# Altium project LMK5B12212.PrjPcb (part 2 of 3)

## Sheet LMK5B12212_Power.SchDoc
size 431 x 279 mm; Date: Not shown in title block; ApprovedBy: Not shown in title block; CheckedBy: Not shown in title block; Author: Not shown in title block; CompanyName: Not shown in title block; Engineer: Not shown in title block; Organization: Not shown in title block; Address1: Not shown in title block; Address2: Not shown in title block; Address3: Not shown in title block; Address4: Not shown in title block; DocumentNumber: 2; Revision: Use project parameter SCH_Rev; SheetNumber: 2; SheetTotal: 3; PageSetup: Record=PageOptions¦CenterHorizontal=True¦CenterVertical=True¦PrintScale=1.00¦XCorrection=1.00¦YCorrection=1.00¦PrintKind=0¦BorderSize=5000000¦LeftOffset=0¦BottomOffset=0¦Orientation=2¦PaperLength=1000¦PaperWidth=1000¦Scale=100¦PaperSource=15¦PrintQuality=600¦MediaType=1¦DitherType=10¦PaperKind=Letter¦PrintScaleMode=1
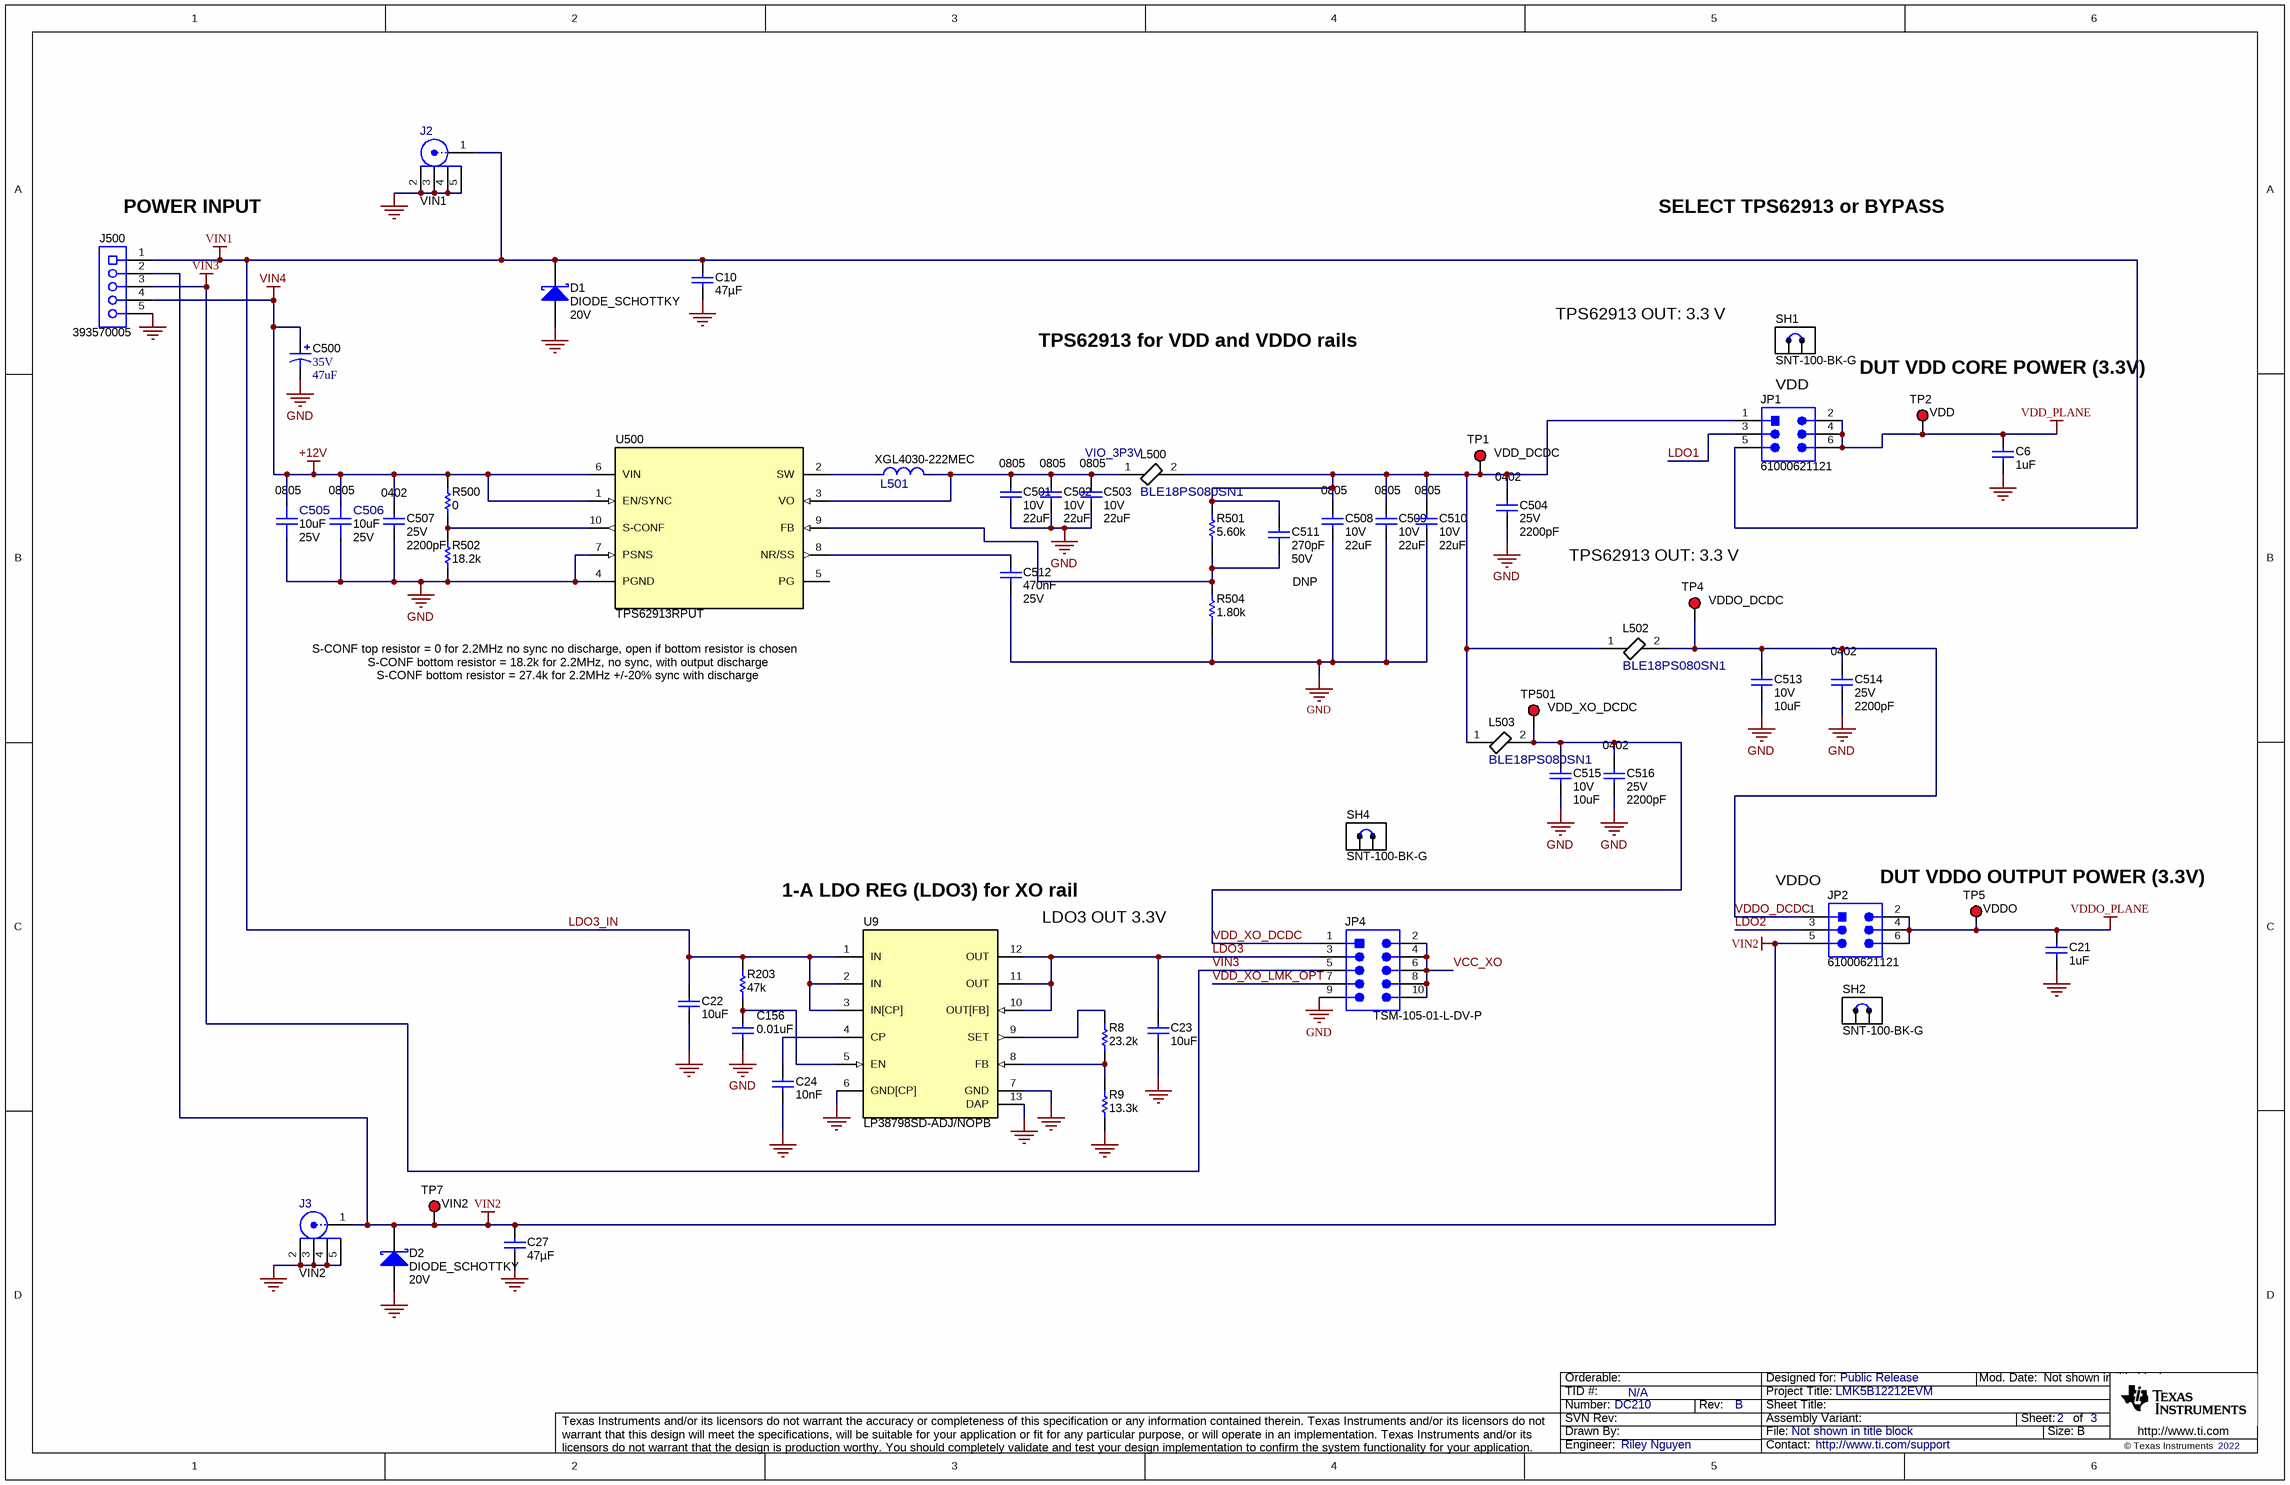
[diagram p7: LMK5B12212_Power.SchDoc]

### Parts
C6  ValueDisplayed: 1uF  [0603]  (hidden comment: Capacitor)
C10  ValueDisplayed: 47µF  [0805_HV]  (hidden comment: GRM21BR61A476ME15L)
C21  ValueDisplayed: 1uF  [0603]  (hidden comment: Capacitor)
C22  ValueDisplayed: 10uF  [0603]  (hidden comment: Capacitor)
C23  ValueDisplayed: 10uF  [0603]  (hidden comment: Capacitor)
C24  ValueDisplayed: 10nF  [0603]  (hidden comment: Capacitor)
C27  ValueDisplayed: 47µF  [0805_HV]  (hidden comment: GRM21BR61A476ME15L)
C156  ValueDisplayed: 0.01uF  [0603]  (hidden comment: Capacitor)
C500  VDC_V: 35V  ValueDisplayed: 47uF  [7343-43]  (hidden comment: T495X476K035ATE300)
C501  Cap_Case: 0805  VDC_V: 10V  ValueDisplayed: 22uF  [0805L]  (hidden comment: C2012X7S1A226M125AC)
C502  Cap_Case: 0805  VDC_V: 10V  ValueDisplayed: 22uF  [0805L]  (hidden comment: C2012X7S1A226M125AC)
C503  Cap_Case: 0805  VDC_V: 10V  ValueDisplayed: 22uF  [0805L]  (hidden comment: C2012X7S1A226M125AC)
C504  VDC_V: 25V  ValueDisplayed: 2200pF  [0402]  (hidden comment: GRM155R71E222KA01D)
C505  PackageReference: 0805  ValueDisplayed: 10uF  VDC_V: 25V  [FP-C2012X7S1E106K125AC_0805-MFG]  (hidden comment: C2012X7S1E106K125AC)
C506  PackageReference: 0805  ValueDisplayed: 10uF  VDC_V: 25V  [FP-C2012X7S1E106K125AC_0805-MFG]  (hidden comment: C2012X7S1E106K125AC)
C507  VDC_V: 25V  ValueDisplayed: 2200pF  [0402]  (hidden comment: GRM155R71E222KA01D)
C508  Cap_Case: 0805  VDC_V: 10V  ValueDisplayed: 22uF  [0805L]  (hidden comment: C2012X7S1A226M125AC)
C509  Cap_Case: 0805  VDC_V: 10V  ValueDisplayed: 22uF  [0805L]  (hidden comment: C2012X7S1A226M125AC)
C510  Cap_Case: 0805  VDC_V: 10V  ValueDisplayed: 22uF  [0805L]  (hidden comment: C2012X7S1A226M125AC)
C511  Cap_F: 270pF  VDC_V: 50V  [0402]  (hidden comment: UMK105CG271JV-F)
C512  Cap_F: 470nF  VDC_V: 25V  [0603]  (hidden comment: C1608X7R1E474K080AE)
C513  VDC_V: 10V  ValueDisplayed: 10uF  [0603]  (hidden comment: GRM188Z71A106MA73D)
C514  VDC_V: 25V  ValueDisplayed: 2200pF  [0402]  (hidden comment: GRM155R71E222KA01D)
C515  VDC_V: 10V  ValueDisplayed: 10uF  [0603]  (hidden comment: GRM188Z71A106MA73D)
C516  VDC_V: 25V  ValueDisplayed: 2200pF  [0402]  (hidden comment: GRM155R71E222KA01D)
D1  DIODE_SCHOTTKY  value 20V  [SMA]
D2  DIODE_SCHOTTKY  value 20V  [SMA]
J2  VIN1  [FP-CON-SMA-EDGE-S_CONN_JACK-MFG]
J3  VIN2  [FP-CON-SMA-EDGE-S_CONN_JACK-MFG]
J500  393570005  [Molex_0393570005]
JP1  61000621121  [Wurth_61000621121]
JP2  61000621121  [Wurth_61000621121]
JP4  TSM-105-01-L-DV-P  [Samtec_TSM-105-01-x-DV]
L500  BLE18PS080SN1  [FP-BLE18PS080SN1_0603-MFG]
L501  XGL4030-222MEC  [FP-XGL4030-222MEC_SMT_IND_4MM0_4MM0-MFG]
L502  BLE18PS080SN1  [FP-BLE18PS080SN1_0603-MFG]
L503  BLE18PS080SN1  [FP-BLE18PS080SN1_0603-MFG]
R8  ValueDisplayed: 23.2k  [0603]  (hidden comment: CRCW060323K2FKEA)
R9  ValueDisplayed: 13.3k  [0603]  (hidden comment: CRCW060313K3FKEA)
R203  ValueDisplayed: 47k  [0603]  (hidden comment: Resistor)
R500  ValueDisplayed: 0  [0603]  (hidden comment: ERJ-3GEY0R00V)
R501  ValueDisplayed: 5.60k  [0603]  (hidden comment: RG1608P-562-B-T5)
R502  ValueDisplayed: 18.2k  [0603]  (hidden comment: CRCW060318K2FKEA)
R504  ValueDisplayed: 1.80k  [0603]  (hidden comment: RT0603BRD071K8L)
SH1  SNT-100-BK-G  [SNT-100-BK-G]
SH2  SNT-100-BK-G  [SNT-100-BK-G]
SH4  SNT-100-BK-G  [SNT-100-BK-G]
TP1  VDD_DCDC  [Keystone5000]
TP2  VDD  [Keystone5000]
TP4  VDDO_DCDC  [Keystone5000]
TP5  VDDO  [Keystone5000]
TP7  VIN2  [Keystone5000]
TP501  VDD_XO_DCDC  [Keystone5000]
U9  LP38798SD-ADJ/NOPB  [DNT0012B]
U500  TPS62913RPUT  [RPU0010A]

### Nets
+12V: C500.1(+) C505.2 C506.2 C507.1 J500.4 R500.2 U500.1(EN/SYNC) U500.6(VIN)  [also labelled VIN4]
GND: C6.1 C10.2 C21.1 C22.2 C23.2 C24.2 C27.2 C156.2 C500.2(-) C501.2 C502.2 C503.2 C504.2 C505.1 C506.1 C507.2 C508.2 C509.2 C510.2 C512.2 C513.2 C514.2 C515.2 C516.2 D1.2(A) D2.2(A) J2.2 J2.3 J2.4 J2.5 J3.2 J3.3 J3.4 J3.5 J500.5 JP4.9 R9.1 R502.1 R504.1 U9.6(GND[CP]) U9.7(GND) U9.13(DAP) U500.4(PGND) U500.7(PSNS)
LDO3_IN: C10.1 C22.1 D1.1(K) J2.1 J500.1 JP1.5 R203.1 U9.1(IN) U9.2(IN) U9.3(IN[CP])  [also labelled VIN1]
VCC_XO: JP4.2 JP4.4 JP4.6 JP4.8 JP4.10
VDD_PLANE: C6.2 JP1.2 JP1.4 JP1.6 TP2.1
VDDO_PLANE: C21.2 JP2.2 JP2.4 JP2.6 TP5.1
VIN2: C27.1 D2.1(K) J3.1 J500.2 JP2.5 TP7.1
VIN3: J500.3 JP4.5
LDO1: JP1.3
LDO2: JP2.3
LDO3: C23.1 JP4.3 U9.10(OUT[FB]) U9.11(OUT) U9.12(OUT)
VDD_XO_DCDC: C515.1 C516.1 JP4.1 L503.2 TP501.1
VDD_XO_LMK_OPT: JP4.7
VDDO_DCDC: C513.1 C514.1 JP2.1 L502.2 TP4.1
NetC24_1: C24.1 U9.4(CP)
NetC156_1: C156.1 R203.2 U9.5(EN)
NetC501_1: C501.1 C502.1 C503.1 L500.1 L501.2 U500.3(VO)
NetC504_1: C504.1 C508.1 C509.1 C510.1 C511.1 JP1.1 L500.2 L502.1 L503.1 R501.2 TP1.1
NetC511_2: C511.2 R501.1 R504.2 U500.9(FB)
NetC512_1: C512.1 U500.8(NR/SS)
NetL501_1: L501.1 U500.2(SW)
NetR8_1: R8.1 R9.2 U9.8(FB)
NetR8_2: R8.2 U9.9(SET)
NetR500_1: R500.1 R502.2 U500.10(S-CONF)

Not connected (* = marked no-connect by the designer): U500 5(PG)

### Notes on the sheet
- (near J500) POWER INPUT
- SELECT TPS62913 or BYPASS
- TPS62913 for VDD and VDDO rails
- TPS62913 OUT: 3.3 V
- (near TP2) DUT VDD CORE POWER (3.3V)
- VDD
- VIO_3P3V
- (near TP4) TPS62913 OUT: 3.3 V
- DNP
- S-CONF top resistor = 0 for 2.2MHz no sync no discharge, open if bottom resistor is chosen
- S-CONF bottom resistor = 18.2k for 2.2MHz, no sync, with output discharge
- S-CONF bottom resistor = 27.4k for 2.2MHz +/-20% sync with discharge
- 1-A LDO REG (LDO3) for XO rail
- (near JP2) VDDO
- DUT VDDO OUTPUT POWER (3.3V)
- LDO3 OUT 3.3V

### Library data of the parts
C6 C21 = CMP-0006869-5: CAP, CERM, 1 uF, 10 V, +/- 10%, X5R, 0603; Manufacturer: Kemet; PartNumber: C0603C105K8PACTU; Polarized: N; TaMax_C: 85°C; TaMin_C: -55°C; VDC_V: 10V; Cap_F: 1µF; Value: 1uF; Value1: Unknown; AEC Category: Q200; SizeArea_mm2: 1.28; SizeAreaWB_mm2: 4.68; SizeX_mm: 1.6; SizeY_mm: 0.8; SizeZ_mm: 1; U/M: EA
C10 C27 = CMP-0078699-1: CAP, CERM, 47 µF, 10 V,+/- 20%, X5R, 0805; Manufacturer: MuRata; Polarized: N; Value: 47uF; U/M: EA; VDC_V: 10V; TaMin_C: -55°C; TaMax_C: 85°C; Cap_Case: 0805; SizeArea_mm2: 2.5; SizeAreaWB_mm2: 6.75; SizeX_mm: 2; SizeY_mm: 1.25; SizeZ_mm: 1.45; AEC Category: Q200; Green_Lifecycle: Active; Green_REACh: Passed
C22-C24 = CMP-0007003-5: CAP, CERM, 10 uF, 10 V, +/- 20%, X5R, 0603; PartNumber: C1608X5R1A106M080AC; Manufacturer: TDK; Polarized: N; Value: 10uF; U/M: EA; Cap_F: 10µF; ESR_ohm: 7.8m; Value1: 0.0078 ohm; VDC_V: 10V; IRMS_A: 1.85A; TaMin_C: -55°C; TaMax_C: 85°C; SizeArea_mm2: 1.28; SizeAreaWB_mm2: 4.68; SizeX_mm: 1.6; SizeY_mm: 0.8; SizeZ_mm: 1; AEC Category: Q200
C156 = CMP-0006850-4: CAP, CERM, 0.01 uF, 50 V, +/- 5%, X7R, 0603; PartNumber: C0603C103J5RACTU; Manufacturer: Kemet; Polarized: N; Value: 0.01uF; U/M: EA; Cap_F: 10nF; Value1: Unknown; VDC_V: 50V; TaMin_C: -55°C; TaMax_C: 125°C; SizeArea_mm2: 1.28; SizeAreaWB_mm2: 4.68; SizeX_mm: 1.6; SizeY_mm: 0.8; SizeZ_mm: 1; AEC Category: Q200
C500 = CMP-0011835-2: CAP, TA, 47 uF, 35 V, +/- 10%, 0.3 ohm, SMD; Manufacturer: Kemet; TaMin_C: -55°C; ESR_ohm: 3d; Polarized: Y; SizeAreaWB_mm2: 58.59; Value1: 0.3 ohm; U/M: EA; Value: 47uF; TaMax_C: 125°C; SizeZ_mm: 4.3; SizeX_mm: 7.3; Cap_Case: X; SizeArea_mm2: 31.39; CompType: Capacitor; Cap_F: 47µF; IRMS_A: 6.67dA; AEC Category: Q200
C501-C503 C508-C510 = CMP-0007890-1: CAP, CERM, 22 uF, 10 V, +/- 20%, X7S, 0805; Manufacturer: TDK; TaMin_C: -55°C; ESR_ohm: 2.05m; Polarized: N; SizeAreaWB_mm2: 6.75; Value1: 0.00205 ohm; U/M: EA; Value: 22uF; TaMax_C: 125°C; SizeZ_mm: 1.45; SizeX_mm: 2; SizeY_mm: 1.25; SizeArea_mm2: 2.5; Cap_F: 22µF; IRMS_A: 4.55587A; AEC Category: Q200
C504 C507 C514 C516 = CMP-0006663-2: CAP, CERM, 2200 pF, 25 V, +/- 10%, X7R, 0402; Manufacturer: MuRata; TaMin_C: -55°C; Polarized: N; SizeAreaWB_mm2: 3; Value1: Unknown; U/M: EA; Value: 2200pF; TaMax_C: 125°C; SizeZ_mm: 0.6; SizeX_mm: 1; SizeY_mm: 0.5; Cap_F: 2.2nF; AEC Category: Q200
C505 C506 = CMP-0089528-1: 10µF ±10% 25V Ceramic Capacitor X7S 0805 (2012 Metric); Manufacturer: TDK; TempCo: 22%; SizeZ_mm: 1.5mm; AEC Qualified: No
C511 = CMP-0087076-3: CAP CER 270PF 50V NP0 0402; Manufacturer: Taiyo Yuden; Tolerance_%: 5%; SizeZ_mm: 0.55mm; AEC Qualified: No; TempCo: 30ppm/°C
C512 = CMP-0750175-1: CAP, CERM, 0.47 µF, 25 V,+/- 10%, X7R, 0603; Manufacturer: TDK; AEC Qualified: N; TaMax_C: 125°C; U/M: EA; AEC Category: Q200; Value: 0.47uF; SizeX_mm: 1.6; SizeAreaWB_mm2: 4.68; SizeZ_mm: 1; SizeY_mm: 0.8; SizeArea_mm2: 1.28; ValueDisplayed: 0.47µF; TaMin_C: -55°C
C513 C515 = CMP-0007497-5: CAP, CERM, 10 uF, 10 V, +/- 20%, X7R, 0603; Manufacturer: MuRata; TaMin_C: -55°C; Polarized: N; SizeAreaWB_mm2: 4.68; Value1: Unknown; U/M: EA; Value: 10uF; TaMax_C: 125°C; SizeZ_mm: 1; SizeX_mm: 1.6; SizeY_mm: 0.8; SizeArea_mm2: 1.28; Cap_F: 10µF; AEC Category: Q200
D1 D2 = CMP-0028399-2: Diode, Schottky, 20 V, 2 A, SMA; PartNumber: B220A-13-F; Manufacturer: Diodes Inc.; Vf_V: 5dV; Value1: 2A; Value2: 0.5V; TJmax_C: 150°C; RJC_CperW: 20; AEC Category: Q101; Green_Lifecycle: Active; Green_REACh: Passed; SizeArea_mm2: 16.3228; SizeAreaWB_mm2: 37.3428; SizeX_mm: 5.59; SizeY_mm: 2.92; SizeZ_mm: 2.87
J2 J3 = CMP-0088000-4: CONN SMA JACK STR EDGE MNT; Manufacturer: RF Solutions Ltd.; PartNumber: CON-SMA-EDGE-S; ContactFinish: Gold; Shrouded: true
J500 = CMP-0080926-1: Terminal Block, 3.5mm, 5x1, Tin, TH; Manufacturer: Molex; Pitch_mm: 3.5; Gender: Female; Voltage_V: 300V; Row_Count: 1; Current_A: 17.5A; Cert_UL: Y
JP1 JP2 = CMP-0079534-2: Header, 2.54mm, 3x2, Gold, SMT; Manufacturer: Wurth Elektronik; Pitch_mm: 2.54; Gender: Male; Cert_UL: Y; Current_A: 3A; Voltage_V: 250V; Shrouded: N; Row_Count: 2
JP4 = CMP-0055598-2: Header, 2.54mm, 5x2, Gold, SMT; Manufacturer: Samtec; Current_A: 5.4A; Green_Lifecycle: Active; Shrouded: N; Gender: Male; Cert_CSA: Y; Green_REACh: Passed; Voltage_V: 475V; Row_Count: 2; RowSpacing_mm: 2.54
L500 L502 L503 = CMP-0087072-1: Bead inductor BLE series, 8A; Manufacturer: Murata; SizeZ_mm: 0.75mm; AEC Qualified: No; Material: Ferrite
L501 = CMP-0089541-1: Inductor Power Shielded Wirewound 2.2uH 20% 1MHz Composite 8.7A 15mOhm DCR Automotive T/R; Manufacturer: Coilcraft; Shrouded: true; SizeZ_mm: 3.1mm; AEC Grade: Grade 1; AEC Qualified: Yes; Isat: 3.1A; Ind_H: 2.2µH; Self Resonant Frequency: 40MHz; DCR_ohm: 0.015; Standoff Height: 0.16mm; TaMin_C: -40°C; TaMax_C: +125°C
R8 = CMP-0022228-4: RES, 23.2 k, 1%, 0.1 W, AEC-Q200 Grade 0, 0603; Manufacturer: Vishay-Dale; Value: 23.2k; Value_Code: 23k2; Power_W: 100mW; Value2: 0.1W; VDC_V: 75V; TempCo: 100 ppm/C; EIA_Code: E96; SizeArea_mm2: 1.28; SizeX_mm: 1.6; SizeY_mm: 0.8; SizeZ_mm: 1; AEC Category: Q200; AEC Qualified: Y; AEC Grade: 0
R9 = CMP-0022043-4: RES, 13.3 k, 1%, 0.1 W, AEC-Q200 Grade 0, 0603; Manufacturer: Vishay-Dale; Value: 13.3k; Value_Code: 13k3; Power_W: 100mW; Value2: 0.1W; VDC_V: 75V; TempCo: 100 ppm/C; EIA_Code: E96; SizeArea_mm2: 1.28; SizeX_mm: 1.6; SizeY_mm: 0.8; SizeZ_mm: 1; AEC Category: Q200; AEC Qualified: Y; AEC Grade: 0
R203 = CMP-0025814-4: RES, 47 k, 5%, 0.1 W, AEC-Q200 Grade 0, 0603; PartNumber: CRCW060347K0JNEA; Manufacturer: Vishay-Dale; Value: 47k; Value_Code: 47k0; Power_W: 100mW; Value2: 0.1W; VDC_V: 75V; TempCo: 200 ppm/C; EIA_Code: E24; SizeArea_mm2: 1.28; SizeX_mm: 1.6; SizeY_mm: 0.8; SizeZ_mm: 1; AEC Category: Q200; AEC Qualified: Y; AEC Grade: 0
R500 = CMP-0025874-4: RES, 0, 5%, 0.1 W, AEC-Q200 Grade 0, 0603; Manufacturer: Panasonic; Power_W: 100mW; TempCo: 600 ppm/C; Value_Code: 0000; Value: 0; EIA_Code: E24; SizeX_mm: 1.6; SizeY_mm: 0.8; SizeZ_mm: 1; Value2: 0.1W; SizeArea_mm2: 1.28; AEC Qualified: Y; VDC_V: 50V; AEC Category: Q200; SizeAreaWB_mm2: 4.68
R501 = CMP-0023576-3: RES, 5.60 k, 0.1%, 0.1 W, 0603; Manufacturer: Susumu Co Ltd; Power_W: 100mW; TempCo: 25 ppm/C; Value_Code: 5k60; U/M: EA; Value: 5.60k; Res_ohm: 5.6k; SizeX_mm: 1.6; SizeY_mm: 0.8; SizeZ_mm: 1; Value2: 0.1W; SizeArea_mm2: 1.28; VDC_V: 75V; AEC Category: Q200
R502 = CMP-0022097-4: RES, 18.2 k, 1%, 0.1 W, AEC-Q200 Grade 0, 0603; Manufacturer: Vishay-Dale; Power_W: 100mW; TempCo: 100 ppm/C; Value_Code: 18k2; Value: 18.2k; EIA_Code: E96; SizeX_mm: 1.6; SizeY_mm: 0.8; SizeZ_mm: 1; Value2: 0.1W; SizeArea_mm2: 1.28; AEC Qualified: Y; VDC_V: 75V; AEC Category: Q200; AEC Grade: 0
R504 = CMP-0023914-3: RES, 1.80 k, 0.1%, 0.1 W, 0603; Manufacturer: Yageo America; Power_W: 100mW; TempCo: 25 ppm/C; Value_Code: 1k80; U/M: EA; Value: 1.80k; EIA_Code: E192; Res_ohm: 1.8k; SizeX_mm: 1.6; SizeY_mm: 0.8; SizeZ_mm: 1; Value2: 0.1W; SizeArea_mm2: 1.28; VDC_V: 75V; AEC Category: Q200
SH1 SH2 SH4 = CMP-0003623-3: Shunt, 100mil, Gold plated, Black; Manufacturer: Samtec; Alternate Manufacturer: 3M; Alternate PartNumber: 969102-0000-DA; Value: 1x2; Note: You can "mate" this to a header by matching the designator.  i.e. use SH-J3 for header J3
TP1 TP2 TP4 TP5 TP7 TP501 = CMP-0055137-1: Test Point, Miniature, Red, TH; Manufacturer: Keystone; CNHeader: FALSE; ContactFinish: Silver; CT: TRUE; Green_Lifecycle: Active; Green_REACh: Passed
U9 = CMP-0066007-2: 800-mA Ultra-Low-Noise, High-PSRR LDO, DNT0012B (WSON-12); Manufacturer: Texas Instruments; SizeZ_mm: 0.8; SizeX_mm: 4.0; SizeArea_mm2: 16.0; CompType: IC; U/M: EA; SizeAreaWB_mm2: 25.0
U500 = CMP-0860321-2: 3A Low Noise and Low Ripple buck converter, RPU0010A (VQFN-10); Alternate Manufacturer: Texas Instruments; SizeArea_mm2: 4; SizeAreaWB_mm2: 9; AEC Category: Q200; SizeY_mm: 2; CompType: IC; SizeZ_mm: 1; AEC Qualified: N

## Sheet LMK5B12212_Power_Alternate.SchDoc
size 431 x 279 mm; Date: Not shown in title block; ApprovedBy: Not shown in title block; CheckedBy: Not shown in title block; Author: Not shown in title block; CompanyName: Not shown in title block; Engineer: Not shown in title block; Organization: Not shown in title block; Address1: Not shown in title block; Address2: Not shown in title block; Address3: Not shown in title block; Address4: Not shown in title block; DocumentNumber: 2; Revision: Use project parameter SCH_Rev; SheetNumber: 2; SheetTotal: 3; PageSetup: Record=PageOptions¦CenterHorizontal=True¦CenterVertical=True¦PrintScale=1.00¦XCorrection=1.00¦YCorrection=1.00¦PrintKind=0¦BorderSize=5000000¦LeftOffset=0¦BottomOffset=0¦Orientation=2¦PaperLength=1000¦PaperWidth=1000¦Scale=100¦PaperSource=15¦PrintQuality=600¦MediaType=1¦DitherType=10¦PaperKind=Letter¦PrintScaleMode=1
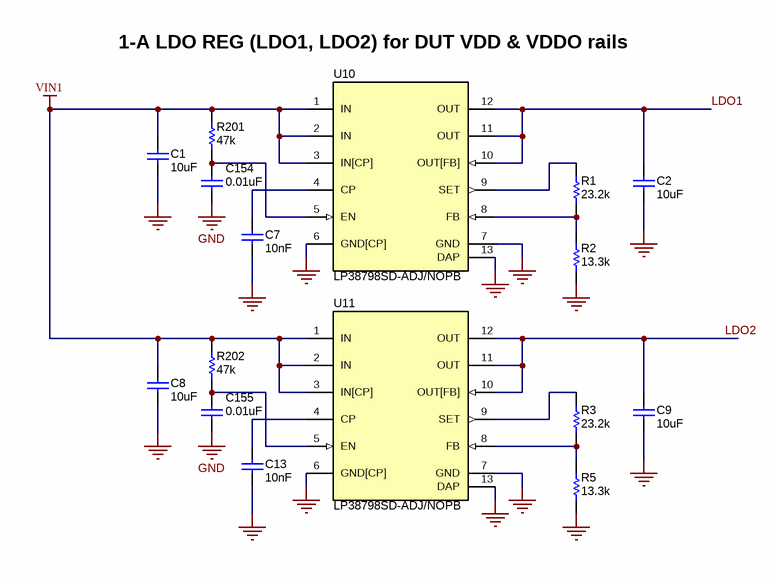
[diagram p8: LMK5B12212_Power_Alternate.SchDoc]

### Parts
C1  ValueDisplayed: 10uF  [0603]  (hidden comment: Capacitor)
C2  ValueDisplayed: 10uF  [0603]  (hidden comment: Capacitor)
C7  ValueDisplayed: 10nF  [0603]  (hidden comment: Capacitor)
C8  ValueDisplayed: 10uF  [0603]  (hidden comment: Capacitor)
C9  ValueDisplayed: 10uF  [0603]  (hidden comment: Capacitor)
C13  ValueDisplayed: 10nF  [0603]  (hidden comment: Capacitor)
C154  ValueDisplayed: 0.01uF  [0603]  (hidden comment: Capacitor)
C155  ValueDisplayed: 0.01uF  [0603]  (hidden comment: Capacitor)
R1  ValueDisplayed: 23.2k  [0603]  (hidden comment: CRCW060323K2FKEA)
R2  ValueDisplayed: 13.3k  [0603]  (hidden comment: CRCW060313K3FKEA)
R3  ValueDisplayed: 23.2k  [0603]  (hidden comment: CRCW060323K2FKEA)
R5  ValueDisplayed: 13.3k  [0603]  (hidden comment: CRCW060313K3FKEA)
R201  ValueDisplayed: 47k  [0603]  (hidden comment: Resistor)
R202  ValueDisplayed: 47k  [0603]  (hidden comment: Resistor)
U10  LP38798SD-ADJ/NOPB  [DNT0012B]
U11  LP38798SD-ADJ/NOPB  [DNT0012B]

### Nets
GND: C1.2 C2.2 C7.2 C8.2 C9.2 C13.2 C154.2 C155.2 R2.1 R5.1 U10.6(GND[CP]) U10.7(GND) U10.13(DAP) U11.6(GND[CP]) U11.7(GND) U11.13(DAP)
VIN1: C1.1 C8.1 R201.1 R202.1 U10.1(IN) U10.2(IN) U10.3(IN[CP]) U11.1(IN) U11.2(IN) U11.3(IN[CP])  [project net LDO3_IN]
LDO1: C2.1 U10.10(OUT[FB]) U10.11(OUT) U10.12(OUT)
LDO2: C9.1 U11.10(OUT[FB]) U11.11(OUT) U11.12(OUT)
NetC7_1: C7.1 U10.4(CP)
NetC13_1: C13.1 U11.4(CP)
NetC154_1: C154.1 R201.2 U10.5(EN)
NetC155_1: C155.1 R202.2 U11.5(EN)
NetR1_1: R1.1 R2.2 U10.8(FB)
NetR1_2: R1.2 U10.9(SET)
NetR3_1: R3.1 R5.2 U11.8(FB)
NetR3_2: R3.2 U11.9(SET)

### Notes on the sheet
- 1-A LDO REG (LDO1, LDO2) for DUT VDD & VDDO rails

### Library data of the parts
C1 C2 C7-C9 C13 = CMP-0007003-5: as C22 on sheet LMK5B12212_Power
C154 C155 = CMP-0006850-4: as C156 on sheet LMK5B12212_Power
R1 R3 = CMP-0022228-4: as R8 on sheet LMK5B12212_Power
R2 R5 = CMP-0022043-4: as R9 on sheet LMK5B12212_Power
R201 R202 = CMP-0025814-4: as R203 on sheet LMK5B12212_Power
U10 U11 = CMP-0066007-2: as U9 on sheet LMK5B12212_Power

## Sheet LMK5B12212_PowerDist.SchDoc
size 431 x 279 mm; Date: Not shown in title block; ApprovedBy: Not shown in title block; CheckedBy: Not shown in title block; Author: Not shown in title block; CompanyName: Not shown in title block; Engineer: Not shown in title block; Organization: Not shown in title block; Address1: Not shown in title block; Address2: Not shown in title block; Address3: Not shown in title block; Address4: Not shown in title block; DocumentNumber: 2; Revision: Use project parameter SCH_Rev; SheetNumber: 2; SheetTotal: 3; PageSetup: Record=PageOptions¦CenterHorizontal=True¦CenterVertical=True¦PrintScale=1.00¦XCorrection=1.00¦YCorrection=1.00¦PrintKind=0¦BorderSize=5000000¦LeftOffset=0¦BottomOffset=0¦Orientation=2¦PaperLength=1000¦PaperWidth=1000¦Scale=100¦PaperSource=15¦PrintQuality=600¦MediaType=1¦DitherType=10¦PaperKind=Letter¦PrintScaleMode=1
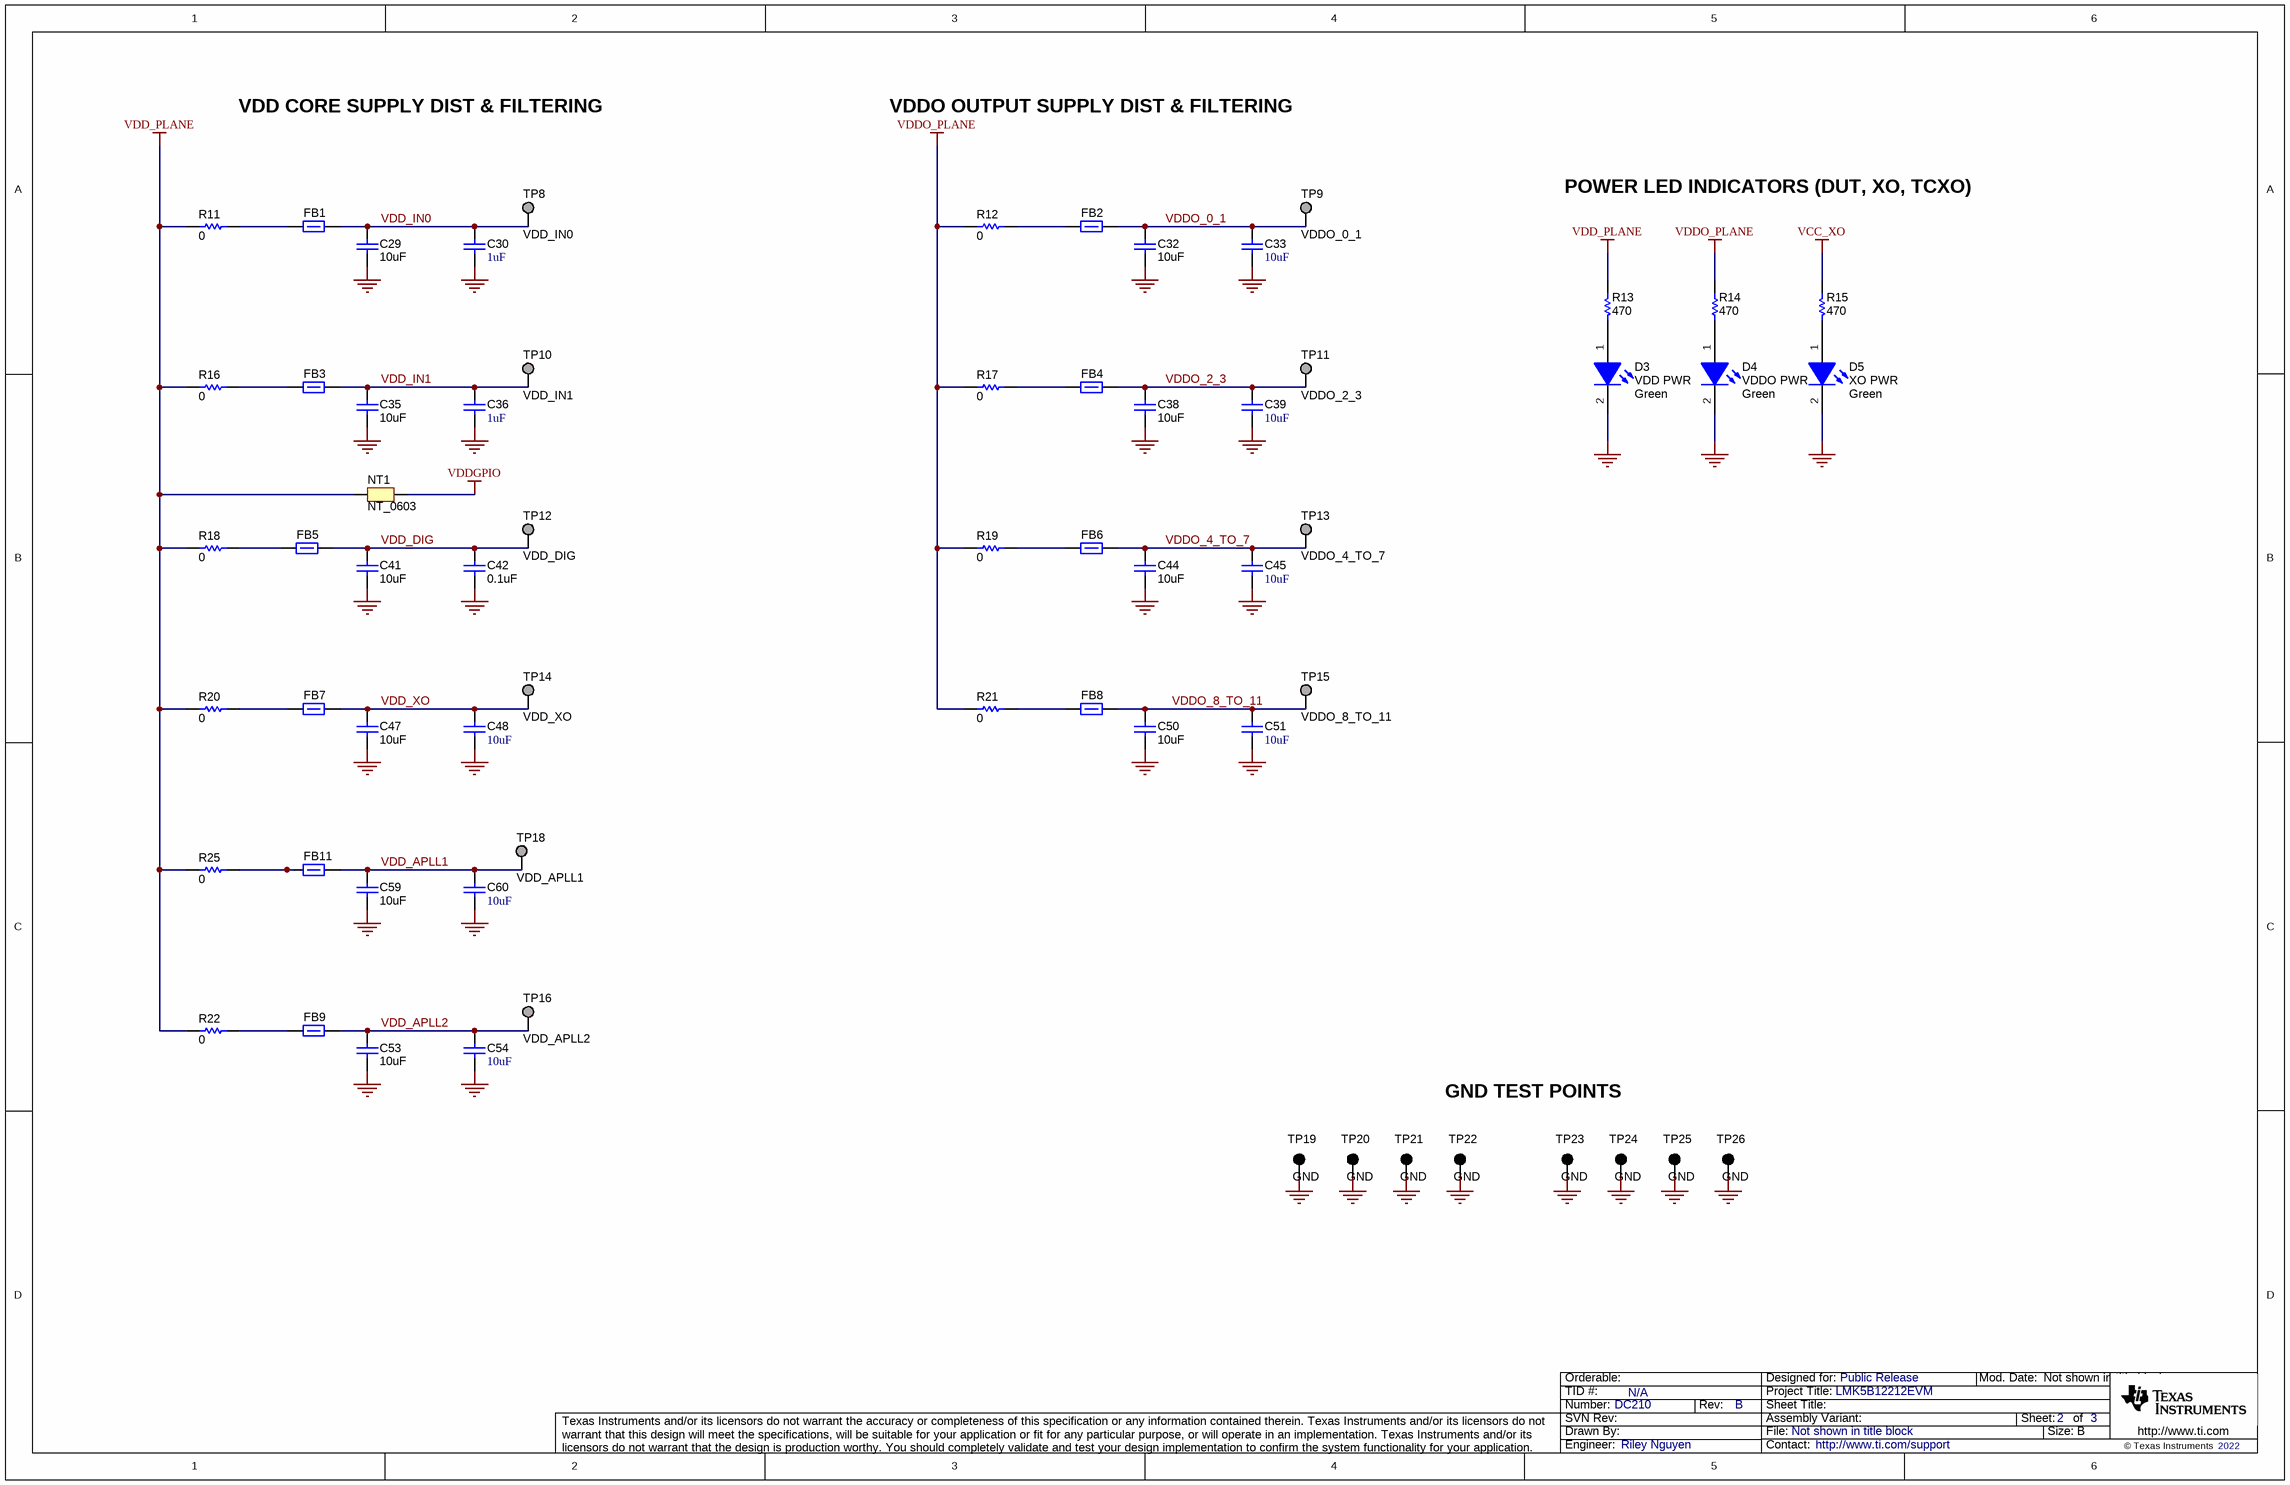
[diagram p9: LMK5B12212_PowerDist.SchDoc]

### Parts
C29  ValueDisplayed: 10uF  [0603L]  (hidden comment: Capacitor)
C30  ValueDisplayed: 1uF  [0402L]  (hidden comment: Capacitor)
C32  ValueDisplayed: 10uF  [0603L]  (hidden comment: Capacitor)
C33  ValueDisplayed: 10uF  [0402L]  (hidden comment: Capacitor)
C35  ValueDisplayed: 10uF  [0603L]  (hidden comment: Capacitor)
C36  ValueDisplayed: 1uF  [0402L]  (hidden comment: Capacitor)
C38  ValueDisplayed: 10uF  [0603L]  (hidden comment: Capacitor)
C39  ValueDisplayed: 10uF  [0402L]  (hidden comment: Capacitor)
C41  ValueDisplayed: 10uF  [0603L]  (hidden comment: Capacitor)
C42  ValueDisplayed: 0.1uF  [0402L]  (hidden comment: Capacitor)
C44  ValueDisplayed: 10uF  [0603L]  (hidden comment: Capacitor)
C45  ValueDisplayed: 10uF  [0402L]  (hidden comment: Capacitor)
C47  ValueDisplayed: 10uF  [0603L]  (hidden comment: Capacitor)
C48  ValueDisplayed: 10uF  [0402L]  (hidden comment: Capacitor)
C50  ValueDisplayed: 10uF  [0603L]  (hidden comment: Capacitor)
C51  ValueDisplayed: 10uF  [0402L]  (hidden comment: Capacitor)
C53  ValueDisplayed: 10uF  [0603L]  (hidden comment: Capacitor)
C54  ValueDisplayed: 10uF  [0402L]  (hidden comment: Capacitor)
C59  ValueDisplayed: 10uF  [0603L]  (hidden comment: Capacitor)
C60  ValueDisplayed: 10uF  [0402L]  (hidden comment: Capacitor)
D3  VDD PWR  value Green  [LED_LTST-C190]
D4  VDDO PWR  value Green  [LED_LTST-C190]
D5  XO PWR  value Green  [LED_LTST-C190]
FB1  BLM18SG221TN1D  [0603L]  (value not drawn)
FB2  BLM18SG221TN1D  [0603L]  (value not drawn)
FB3  BLM18SG221TN1D  [0603L]  (value not drawn)
FB4  BLM18SG221TN1D  [0603L]  (value not drawn)
FB5  BLM18SG221TN1D  [0603L]  (value not drawn)
FB6  BLM18SG221TN1D  [0603L]  (value not drawn)
FB7  BLM18SG221TN1D  [0603L]  (value not drawn)
FB8  BLM18SG221TN1D  [0603L]  (value not drawn)
FB9  BLM18SG221TN1D  [0603L]  (value not drawn)
FB11  BLM18SG221TN1D  [0603L]  (value not drawn)
NT1  NT_0603  [NetTie_0603]  (net tie, no BOM)
R11  ValueDisplayed: 0  [0603]  (hidden comment: CRCW06030000Z0EA)
R12  ValueDisplayed: 0  [0603]  (hidden comment: CRCW06030000Z0EA)
R13  ValueDisplayed: 470  [0603]  (hidden comment: Resistor)
R14  ValueDisplayed: 470  [0603]  (hidden comment: Resistor)
R15  ValueDisplayed: 470  [0603]  (hidden comment: Resistor)
R16  ValueDisplayed: 0  [0603]  (hidden comment: CRCW06030000Z0EA)
R17  ValueDisplayed: 0  [0603]  (hidden comment: CRCW06030000Z0EA)
R18  ValueDisplayed: 0  [0603]  (hidden comment: CRCW06030000Z0EA)
R19  ValueDisplayed: 0  [0603]  (hidden comment: CRCW06030000Z0EA)
R20  ValueDisplayed: 0  [0603]  (hidden comment: CRCW06030000Z0EA)
R21  ValueDisplayed: 0  [0603]  (hidden comment: CRCW06030000Z0EA)
R22  ValueDisplayed: 0  [0603]  (hidden comment: CRCW06030000Z0EA)
R25  ValueDisplayed: 0  [0603]  (hidden comment: CRCW06030000Z0EA)
TP8  VDD_IN0  [TP_SM_1MM]  (no BOM)
TP9  VDDO_0_1  [TP_SM_1MM]  (no BOM)
TP10  VDD_IN1  [TP_SM_1MM]  (no BOM)
TP11  VDDO_2_3  [TP_SM_1MM]  (no BOM)
TP12  VDD_DIG  [TP_SM_1MM]  (no BOM)
TP13  VDDO_4_TO_7  [TP_SM_1MM]  (no BOM)
TP14  VDD_XO  [TP_SM_1MM]  (no BOM)
TP15  VDDO_8_TO_11  [TP_SM_1MM]  (no BOM)
TP16  VDD_APLL2  [TP_SM_1MM]  (no BOM)
TP18  VDD_APLL1  [TP_SM_1MM]  (no BOM)
TP19  GND  [Keystone5001]
TP20  GND  [Keystone5001]
TP21  GND  [Keystone5001]
TP22  GND  [Keystone5001]
TP23  GND  [Keystone5001]
TP24  GND  [Keystone5001]
TP25  GND  [Keystone5001]
TP26  GND  [Keystone5001]

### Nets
GND: C29.2 C30.1 C32.2 C33.1 C35.2 C36.1 C38.2 C39.1 C41.2 C42.1 C44.2 C45.1 C47.2 C48.1 C50.2 C51.1 C53.2 C54.1 C59.2 C60.1 D3.2(K) D4.2(K) D5.2(K) TP19.1 TP20.1 TP21.1 TP22.1 TP23.1 TP24.1 TP25.1 TP26.1
VCC_XO: R15.1
VDD_PLANE: NT1.2 R11.2 R13.1 R16.2 R18.2 R20.2 R22.2 R25.2
VDDGPIO: NT1.1
VDDO_PLANE: R12.2 R14.1 R17.2 R19.2 R21.2
VDD_APLL1: C59.1 C60.2 FB11.2 TP18.1
VDD_APLL2: C53.1 C54.2 FB9.2 TP16.1
VDD_DIG: C41.1 C42.2 FB5.2 TP12.1
VDD_IN0: C29.1 C30.2 FB1.2 TP8.1
VDD_IN1: C35.1 C36.2 FB3.2 TP10.1
VDD_XO: C47.1 C48.2 FB7.2 TP14.1
VDDO_0_1: C32.1 C33.2 FB2.2 TP9.1
VDDO_2_3: C38.1 C39.2 FB4.2 TP11.1
VDDO_4_TO_7: C44.1 C45.2 FB6.2 TP13.1
VDDO_8_TO_11: C50.1 C51.2 FB8.2 TP15.1
NetD3_1: D3.1(A) R13.2
NetD4_1: D4.1(A) R14.2
NetD5_1: D5.1(A) R15.2
NetFB1_1: FB1.1 R11.1
NetFB2_1: FB2.1 R12.1
NetFB3_1: FB3.1 R16.1
NetFB4_1: FB4.1 R17.1
NetFB5_1: FB5.1 R18.1
NetFB6_1: FB6.1 R19.1
NetFB7_1: FB7.1 R20.1
NetFB8_1: FB8.1 R21.1
NetFB9_1: FB9.1 R22.1
NetFB11_1: FB11.1 R25.1

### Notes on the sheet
- VDD CORE SUPPLY DIST & FILTERING
- VDDO OUTPUT SUPPLY DIST & FILTERING
- POWER LED INDICATORS (DUT, XO, TCXO)
- GND TEST POINTS

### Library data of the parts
C29 C32 C35 C38 C41 C44 C47 C50 C53 C59 = CMP-0007003-5: CAP, CERM, 10 uF, 10 V, +/- 20%, X5R, 0603; PartNumber: C1608X5R1A106M080AC; Manufacturer: TDK; Polarized: N; Value: 10uF; U/M: EA; Cap_F: 10µF; ESR_ohm: 7.8m; Value1: 0.0078 ohm; VDC_V: 10V; IRMS_A: 1.85A; TaMin_C: -55°C; TaMax_C: 85°C; Cap_Case: 0603; SizeArea_mm2: 1.28; SizeAreaWB_mm2: 4.68; SizeX_mm: 1.6; SizeY_mm: 0.8; SizeZ_mm: 1; AEC Category: Q200
C30 C36 = CMP-0064971-2: CAP, CERM, 1 uF, 10 V,+/- 10%, X6S, 0402; PartNumber: GRM155C81A105KA12D; Manufacturer: MuRata; Polarized: N; Value: 1uF; U/M: EA; Cap_F: 1µF; Value1: Unknown; VDC_V: 10V; TaMin_C: -55°C; TaMax_C: 105°C; Cap_Case: 0402; SizeArea_mm2: 0.5; SizeAreaWB_mm2: 3; SizeX_mm: 1; SizeZ_mm: 0.6; AEC Category: Q200
C33 C39 C45 C48 C51 C54 C60 = CMP-0006564-3: CAP, CERM, 10 uF, 10 V, +/- 20%, X5R, 0402; PartNumber: GRM155R61A106ME11D; Manufacturer: MuRata; Polarized: N; Value: 10uF; U/M: EA; Cap_F: 10µF; Value1: Unknown; VDC_V: 10V; TaMin_C: -55°C; TaMax_C: 85°C; Cap_Case: 0402; SizeArea_mm2: 0.5; SizeAreaWB_mm2: 3; SizeX_mm: 1; SizeZ_mm: 0.6; AEC Category: Q200
C42 = CMP-0006259-2: CAP, CERM, 0.1 uF, 10 V, +/- 10%, X5R, 0402; PartNumber: C1005X5R1A104K050BA; Manufacturer: TDK; Polarized: N; Value: 0.1uF; U/M: EA; Cap_F: 100nF; Value1: Unknown; VDC_V: 10V; TaMin_C: -55°C; TaMax_C: 85°C; Cap_Case: 0402; SizeArea_mm2: 0.5; SizeAreaWB_mm2: 3; SizeX_mm: 1; SizeZ_mm: 0.6; AEC Category: Q200
D3-D5 = CMP-0002827-3: LED, Green, SMD; Manufacturer: Lite-On; PartNumber: LTST-C190GKT; Vf_V: 2.1V; Io_A: 20mA; Power_TotalModule: 100mW; Value1: 0.1W
FB1-FB9 FB11 = CMP-0003353-2: Ferrite Bead, 220 ohm @ 100 MHz, 2.5 A, 0603; Manufacturer: MuRata; Value: 220 ohm; Imax_A: 2.5A; DCR_ohm: 0.04; Value1: 0.04 ohm; ZTyp@100MHz_Ohm: 220; SizeArea_mm2: 1.28; SizeAreaWB_mm2: 4.68; SizeX_mm: 1.6; SizeY_mm: 0.8; SizeZ_mm: 1
NT1 = CMP-0078142-3: Single point connection between nets.
R11 R12 R16-R22 R25 = CMP-0025697-4: RES, 0, 5%, 0.1 W, AEC-Q200 Grade 0, 0603; Manufacturer: Vishay-Dale; Power_W: 100mW; TempCo: 200 ppm/C; Value_Code: 0000; Value: 0; EIA_Code: E24; SizeX_mm: 1.6; SizeY_mm: 0.8; SizeZ_mm: 1; Value2: 0.1W; SizeArea_mm2: 1.28; AEC Qualified: Y; VDC_V: 75V; AEC Category: Q200
R13-R15 = CMP-0025813-4: RES, 470, 5%, 0.1 W, AEC-Q200 Grade 0, 0603; PartNumber: CRCW0603470RJNEA; Manufacturer: Vishay-Dale; Value: 470; Value_Code: 470R; Power_W: 100mW; Value2: 0.1W; VDC_V: 75V; TempCo: 200 ppm/C; EIA_Code: E24; SizeArea_mm2: 1.28; SizeX_mm: 1.6; SizeY_mm: 0.8; SizeZ_mm: 1; AEC Category: Q200; AEC Qualified: Y; AEC Grade: 0
TP8-TP16 TP18 = CMP-0003825-1: 1mm Test Point, SMT; Manufacturer: Any
TP19-TP26 = CMP-0055138-1: Test Point, Miniature, Black, TH; Manufacturer: Keystone; ContactFinish: Silver; CNHeader: FALSE; CT: TRUE; Green_Lifecycle: Active; Green_REACh: Passed

## Sheet LMK5B12212_USB2ANY.SchDoc
size 431 x 279 mm; Date: Not shown in title block; ApprovedBy: Not shown in title block; CheckedBy: Not shown in title block; Author: Not shown in title block; CompanyName: Not shown in title block; Engineer: Not shown in title block; Organization: Not shown in title block; Address1: Not shown in title block; Address2: Not shown in title block; Address3: Not shown in title block; Address4: Not shown in title block; DocumentNumber: 2; Revision: Use project parameter SCH_Rev; SheetNumber: 2; SheetTotal: 3; PageSetup: Record=PageOptions¦CenterHorizontal=True¦CenterVertical=True¦PrintScale=1.00¦XCorrection=1.00¦YCorrection=1.00¦PrintKind=0¦BorderSize=5000000¦LeftOffset=0¦BottomOffset=0¦Orientation=2¦PaperLength=1000¦PaperWidth=1000¦Scale=100¦PaperSource=15¦PrintQuality=600¦MediaType=1¦DitherType=10¦PaperKind=Letter¦PrintScaleMode=1
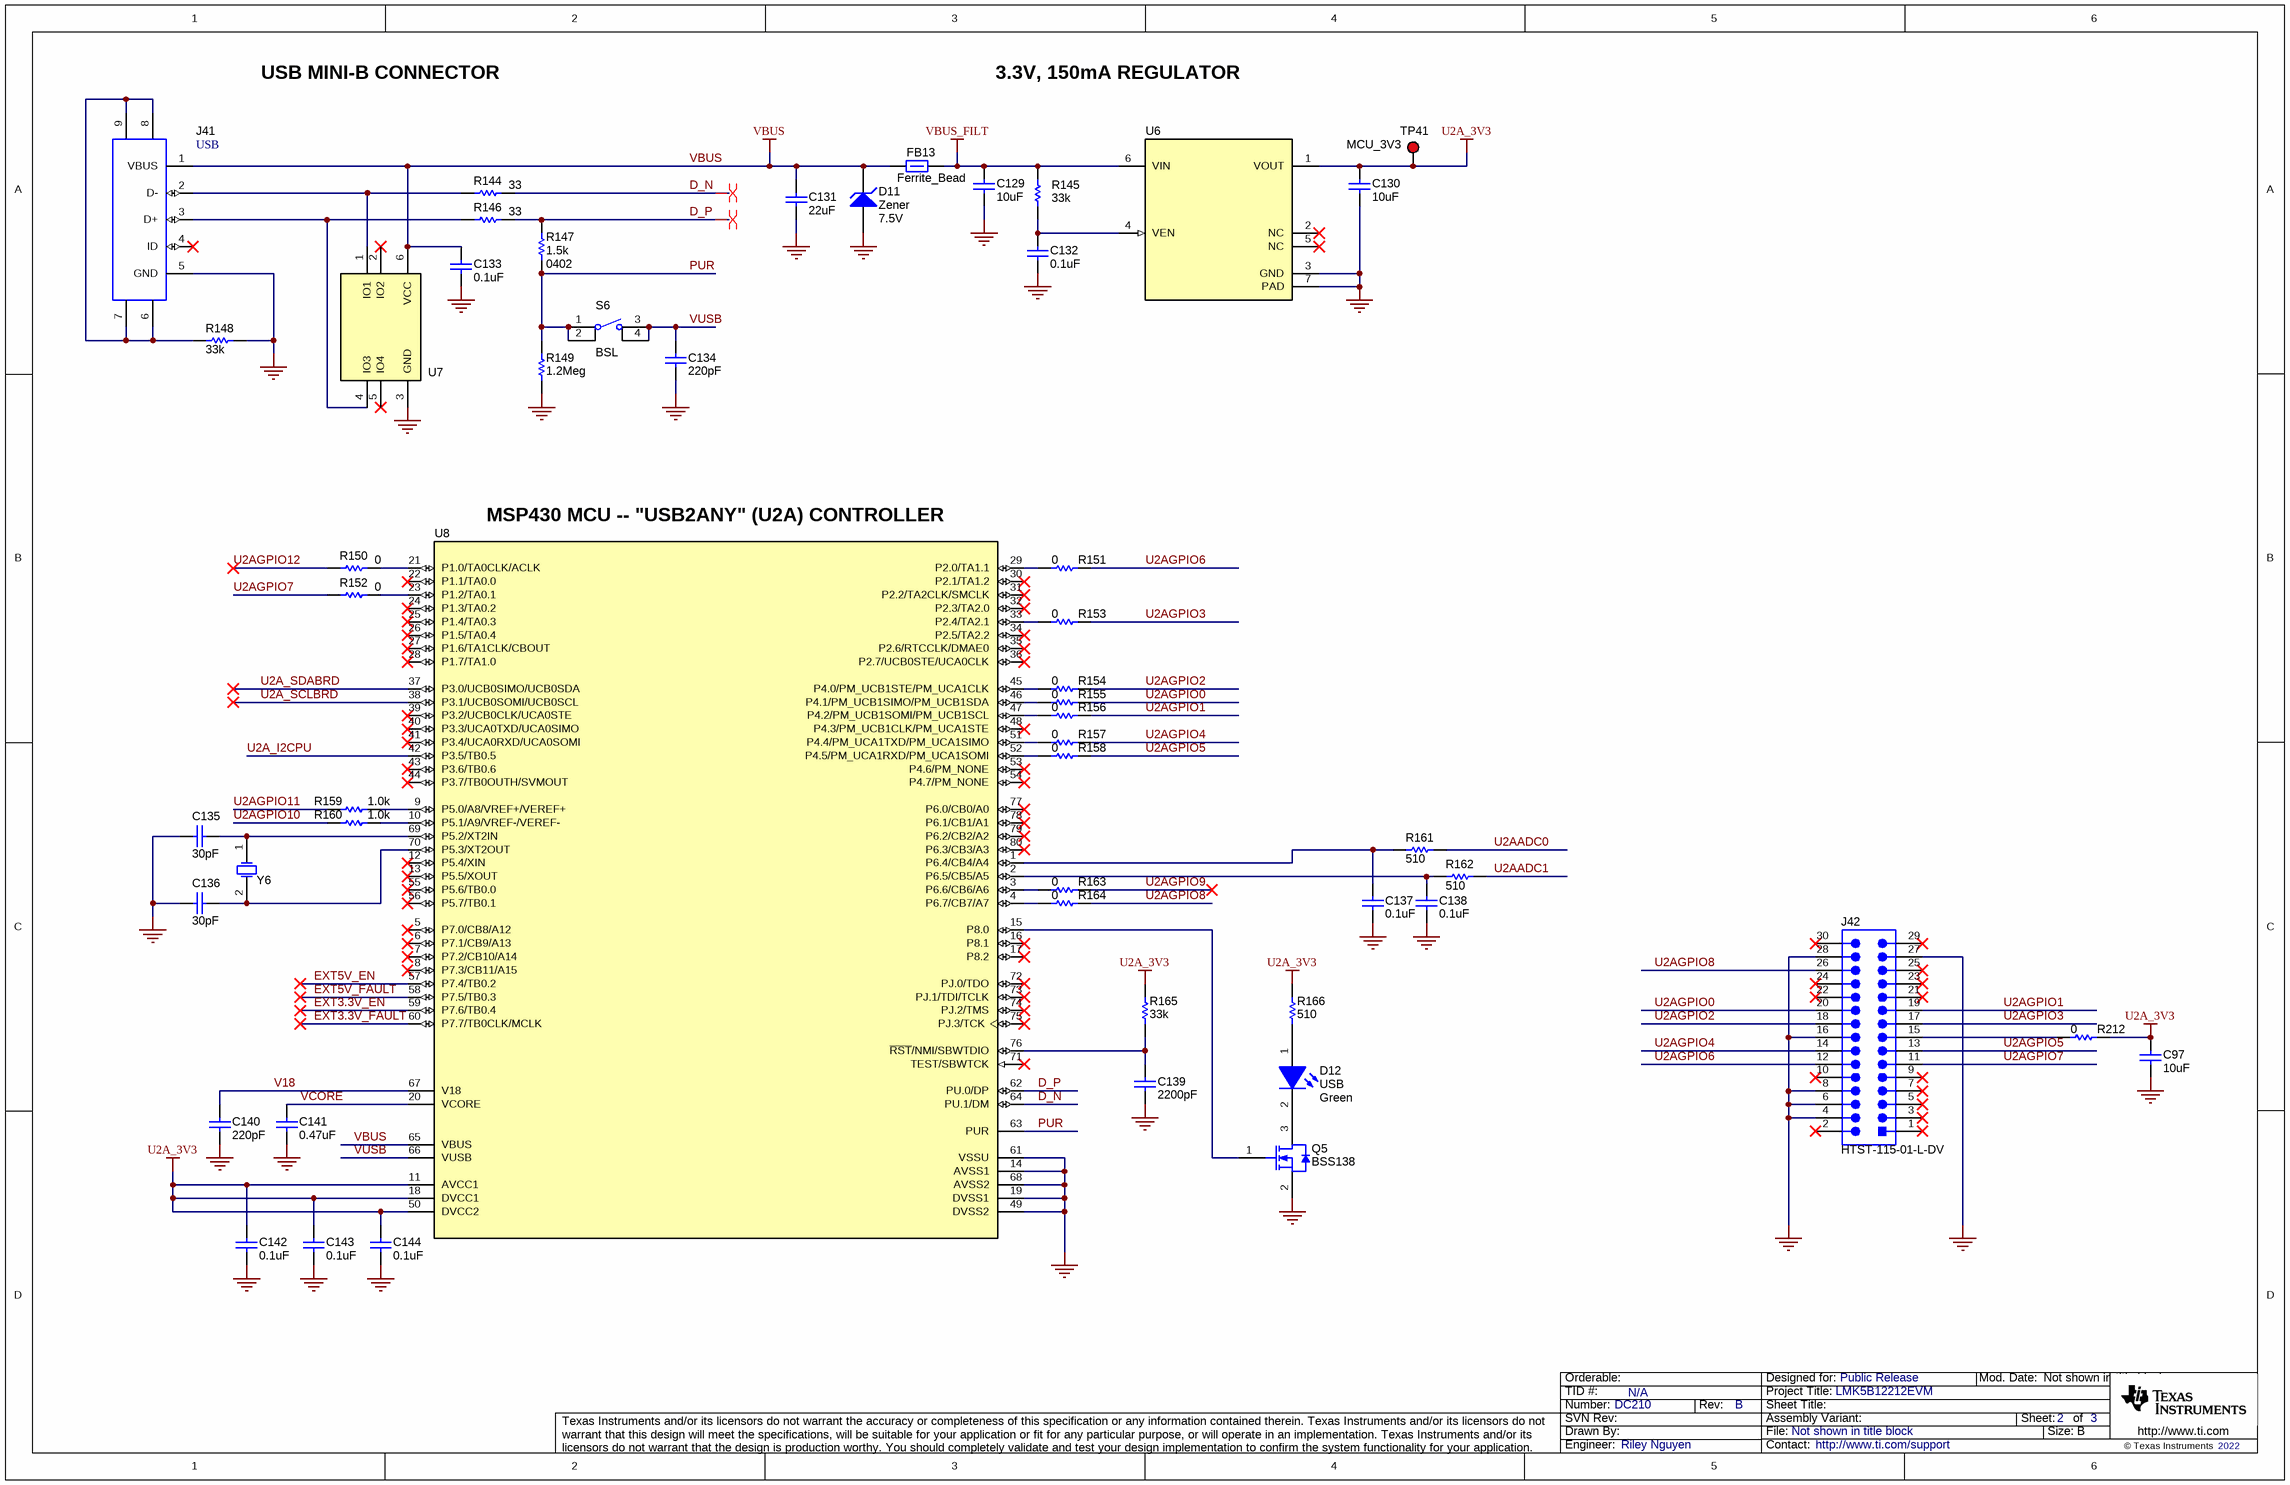
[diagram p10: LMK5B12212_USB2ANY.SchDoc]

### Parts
C97  ValueDisplayed: 10uF  [0603]  (hidden comment: Capacitor)
C129  ValueDisplayed: 10uF  [0603]  (hidden comment: Capacitor)
C130  ValueDisplayed: 10uF  [0603]  (hidden comment: Capacitor)
C131  ValueDisplayed: 22uF  [0805]  (hidden comment: Capacitor)
C132  ValueDisplayed: 0.1uF  [0603]  (hidden comment: Capacitor)
C133  ValueDisplayed: 0.1uF  [0603]  (hidden comment: Capacitor)
C134  ValueDisplayed: 220pF  [0603]  (hidden comment: Capacitor)
C135  ValueDisplayed: 30pF  [0603]  (hidden comment: Capacitor)
C136  ValueDisplayed: 30pF  [0603]  (hidden comment: Capacitor)
C137  ValueDisplayed: 0.1uF  [0603]  (hidden comment: Capacitor)
C138  ValueDisplayed: 0.1uF  [0603]  (hidden comment: Capacitor)
C139  ValueDisplayed: 2200pF  [0603]  (hidden comment: Capacitor)
C140  ValueDisplayed: 220pF  [0603]  (hidden comment: Capacitor)
C141  ValueDisplayed: 0.47uF  [0603]  (hidden comment: Capacitor)
C142  ValueDisplayed: 0.1uF  [0603]  (hidden comment: Capacitor)
C143  ValueDisplayed: 0.1uF  [0603]  (hidden comment: Capacitor)
C144  ValueDisplayed: 0.1uF  [0603]  (hidden comment: Capacitor)
D11  Zener  value 7.5V  [SMB]
D12  USB  value Green  [LED_LTST-C190]
FB13  Ferrite_Bead  [0603]
J41  USB  [CONN_USB-Mini-B-1734035-2]
J42  HTST-115-01-L-DV  [Samtec_HTST-115-01-x-DV]
Q5  BSS138  [SOT-23]
R144  value 33  [0402]  (hidden comment: Resistor)
R145  value 33k  [0603]  (hidden comment: Resistor)
R146  value 33  [0402]  (hidden comment: Resistor)
R147  value 1.5k  [0402]  (hidden comment: Resistor)
R148  value 33k  [0603]  (hidden comment: Resistor)
R149  value 1.2Meg  [0603]  (hidden comment: Resistor)
R150  value 0  [0603]  (hidden comment: Resistor)
R151  value 0  [0603]  (hidden comment: Resistor)
R152  value 0  [0603]  (hidden comment: Resistor)
R153  value 0  [0603]  (hidden comment: Resistor)
R154  value 0  [0603]  (hidden comment: Resistor)
R155  value 0  [0603]  (hidden comment: Resistor)
R156  value 0  [0603]  (hidden comment: Resistor)
R157  value 0  [0603]  (hidden comment: Resistor)
R158  ValueDisplayed: 0  [0603]  (hidden comment: CRCW06030000Z0EA)
R159  ValueDisplayed: 1.0k  [0603]  (hidden comment: CRCW06031K00JNEA)
R160  ValueDisplayed: 1.0k  [0603]  (hidden comment: CRCW06031K00JNEA)
R161  ValueDisplayed: 510  [0603]  (hidden comment: Resistor)
R162  ValueDisplayed: 510  [0603]  (hidden comment: Resistor)
R163  value 0  [0603]  (hidden comment: Resistor)
R164  value 0  [0603]  (hidden comment: Resistor)
R165  value 33k  [0603]  (hidden comment: Resistor)
R166  ValueDisplayed: 510  [0603]  (hidden comment: Resistor)
R212  value 0  [0603]  (hidden comment: Resistor)
S6  BSL  [SW_FSM4JSMA]
TP41  MCU_3V3  [Keystone5000]
U6  LP5900SD-3.3/NOPB  [NGF0006A]  (value not drawn)
U7  TPD4E004DRYR  [DRY0006A]  (value not drawn)
U8  MSP430F5529IPN  [PN0080A_N]  (value not drawn)
Y6  Xtal  [XTAL_CSM-7X]  (value not drawn)

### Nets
GND: C97.2 C129.1 C130.2 C131.2 C132.1 C133.1 C134.1 C135.2 C136.2 C137.1 C138.1 C139.2 C140.1 C141.1 C142.1 C143.1 C144.1 D11.2(A) J41.5(GND) J42.4 J42.6 J42.8 J42.16 J42.27 J42.28 Q5.2(S) R148.2 R149.1 U6.3(GND) U6.7(PAD) U7.3(GND) U8.14(AVSS1) U8.19(DVSS1) U8.49(DVSS2) U8.61(VSSU) U8.68(AVSS2)
U2A_3V3: C97.1 C130.1 C142.2 C143.2 C144.2 R165.1 R166.2 R212.2 TP41.1 U6.1(VOUT) U8.11(AVCC1) U8.18(DVCC1) U8.50(DVCC2)
VBUS: C131.1 C133.2 D11.1(K) FB13.1 J41.1(VBUS) U7.6(VCC) U8.65(VBUS)
VBUS_FILT: C129.2 FB13.2 R145.1 U6.6(VIN)
D_N: R144.1 U8.64(PU.1/DM)
D_P: R146.1 R147.2 U8.62(PU.0/DP)
EXT3.3V_EN: U8.59(P7.6/TB0.4)
EXT3.3V_FAULT: U8.60(P7.7/TB0CLK/MCLK)
EXT5V_EN: U8.57(P7.4/TB0.2)
EXT5V_FAULT: U8.58(P7.5/TB0.3)
PUR: R147.1 R149.2 S6.1 S6.2 U8.63(PUR)
U2A_I2CPU: U8.42(P3.5/TB0.5)
U2A_SCLBRD: U8.38(P3.1/UCB0SOMI/UCB0SCL)
U2A_SDABRD: U8.37(P3.0/UCB0SIMO/UCB0SDA)
U2AADC0: R161.2
U2AADC1: R162.2
U2AGPIO0: J42.20 R155.1
U2AGPIO1: J42.19 R156.1
U2AGPIO2: J42.18 R154.2
U2AGPIO3: J42.17 R153.2
U2AGPIO4: J42.14 R157.2
U2AGPIO5: J42.13 R158.2
U2AGPIO6: J42.12 R151.2
U2AGPIO7: J42.11 R152.2
U2AGPIO8: J42.26 R164.2
U2AGPIO9: R163.2
U2AGPIO10: R160.2
U2AGPIO11: R159.2
U2AGPIO12: R150.2
V18: C140.2 U8.67(V18)
VCORE: C141.2 U8.20(VCORE)
VUSB: C134.2 S6.3 S6.4 U8.66(VUSB)
NetC132_2: C132.2 R145.2 U6.4(VEN)
NetC135_1: C135.1 U8.69(P5.2/XT2IN) Y6.1(OSC1)
NetC136_1: C136.1 U8.70(P5.3/XT2OUT) Y6.2(OSC2)
NetC137_2: C137.2 R161.1 U8.1(P6.4/CB4/A4)
NetC138_2: C138.2 R162.1 U8.2(P6.5/CB5/A5)
NetC139_1: C139.1 R165.2 U8.76(~{RST}/NMI/SBWTDIO)
NetD12_1: D12.1(A) R166.1
NetD12_2: D12.2(K) Q5.3(D)
NetJ41_2: J41.2(D-) R144.2 U7.1(IO1)
NetJ41_3: J41.3(D+) R146.2 U7.4(IO3)
NetJ41_6: J41.6 J41.7 J41.8 J41.9 R148.1
NetJ42_15: J42.15 R212.1
NetQ5_1: Q5.1(G) U8.15(P8.0)
NetR150_1: R150.1 U8.21(P1.0/TA0CLK/ACLK)
NetR151_1: R151.1 U8.29(P2.0/TA1.1)
NetR152_1: R152.1 U8.23(P1.2/TA0.1)
NetR153_1: R153.1 U8.33(P2.4/TA2.1)
NetR154_1: R154.1 U8.45(P4.0/PM_UCB1STE/PM_UCA1CLK)
NetR155_2: R155.2 U8.46(P4.1/PM_UCB1SIMO/PM_UCB1SDA)
NetR156_2: R156.2 U8.47(P4.2/PM_UCB1SOMI/PM_UCB1SCL)
NetR157_1: R157.1 U8.51(P4.4/PM_UCA1TXD/PM_UCA1SIMO)
NetR158_1: R158.1 U8.52(P4.5/PM_UCA1RXD/PM_UCA1SOMI)
NetR159_1: R159.1 U8.9(P5.0/A8/VREF+/VEREF+)
NetR160_1: R160.1 U8.10(P5.1/A9/VREF-/VEREF-)
NetR163_1: R163.1 U8.3(P6.6/CB6/A6)
NetR164_1: R164.1 U8.4(P6.7/CB7/A7)

Not connected (* = marked no-connect by the designer): J41 4(ID)*; J42 1* 2* 3* 5* 7* 9* 10* 21* 22* 23* 24* 25* 29* 30*; U6 2(NC)* 5(NC)*; U7 2(IO2)* 5(IO4)*; U8 5(P7.0/CB8/A12)* 6(P7.1/CB9/A13)* 7(P7.2/CB10/A14)* 8(P7.3/CB11/A15)* 12(P5.4/XIN)* 13(P5.5/XOUT)* 16(P8.1)* 17(P8.2)* 22(P1.1/TA0.0)* 24(P1.3/TA0.2)* 25(P1.4/TA0.3)* 26(P1.5/TA0.4)* 27(P1.6/TA1CLK/CBOUT)* 28(P1.7/TA1.0)* 30(P2.1/TA1.2)* 31(P2.2/TA2CLK/SMCLK)* 32(P2.3/TA2.0)* 34(P2.5/TA2.2)* 35(P2.6/RTCCLK/DMAE0)* 36(P2.7/UCB0STE/UCA0CLK)* 39(P3.2/UCB0CLK/UCA0STE)* 40(P3.3/UCA0TXD/UCA0SIMO)* 41(P3.4/UCA0RXD/UCA0SOMI)* 43(P3.6/TB0.6)* 44(P3.7/TB0OUTH/SVMOUT)* 48(P4.3/PM_UCB1CLK/PM_UCA1STE)* 53(P4.6/PM_NONE)* 54(P4.7/PM_NONE)* 55(P5.6/TB0.0)* 56(P5.7/TB0.1)* 71(TEST/SBWTCK)* 72(PJ.0/TDO)* 73(PJ.1/TDI/TCLK)* 74(PJ.2/TMS)* 75(PJ.3/TCK)* 77(P6.0/CB0/A0)* 78(P6.1/CB1/A1)* 79(P6.2/CB2/A2)* 80(P6.3/CB3/A3)*

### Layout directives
differential pair: D_N, D_P

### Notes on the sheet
- USB MINI-B CONNECTOR
- 3.3V, 150mA REGULATOR
- (near U8) MSP430 MCU -- "USB2ANY" (U2A) CONTROLLER

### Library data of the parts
C97 C130 = CMP-0007003-5: as C22 on sheet LMK5B12212_Power
C129 = CMP-0007003-5: CAP, CERM, 10 uF, 10 V, +/- 20%, X5R, 0603; Manufacturer: TDK; PartNumber: C1608X5R1A106M080AC; ESR_ohm: 7.8m; IRMS_A: 1.85A; Polarized: N; TaMax_C: 85°C; TaMin_C: -55°C; VDC_V: 10V; Cap_F: 10µF; Value: 10uF; Value1: 0.0078 ohm; U/M: EA; SizeArea_mm2: 1.28; SizeAreaWB_mm2: 4.68; SizeX_mm: 1.6; SizeY_mm: 0.8; SizeZ_mm: 1; AEC Category: Q200
C131 = CMP-0008403-2: CAP, CERM, 22 uF, 10 V, +/- 20%, X5R, 0805; PartNumber: LMK212BJ226MG-T; Manufacturer: Taiyo Yuden; Polarized: N; Value: 22uF; U/M: EA; Cap_F: 22µF; Value1: Unknown; VDC_V: 10V; TaMin_C: -55°C; TaMax_C: 85°C; AEC Category: Q200; SizeArea_mm2: 2.5; SizeAreaWB_mm2: 6.75; SizeX_mm: 2; SizeY_mm: 1.25; SizeZ_mm: 1.45
C132 C133 C137 C138 C142-C144 = CMP-0006857-4: CAP, CERM, 0.1 uF, 16 V, +/- 5%, X7R, 0603; PartNumber: C0603C104J4RACTU; Manufacturer: Kemet; Polarized: N; Value: 0.1uF; U/M: EA; Cap_F: 100nF; Value1: Unknown; VDC_V: 16V; TaMin_C: -55°C; TaMax_C: 125°C; AEC Category: Q200; SizeArea_mm2: 1.28; SizeAreaWB_mm2: 4.68; SizeX_mm: 1.6; SizeY_mm: 0.8; SizeZ_mm: 1
C134 C140 = CMP-0006776-4: CAP, CERM, 220 pF, 50 V, +/- 1%, C0G/NP0, 0603; PartNumber: 06035A221FAT2A; Manufacturer: AVX; Polarized: N; Value: 220pF; U/M: EA; ESR_ohm: 0.083; Value1: 0.083 ohm; VDC_V: 50V; TaMin_C: -55°C; TaMax_C: 125°C; AEC Category: Q200; SizeArea_mm2: 1.28; SizeAreaWB_mm2: 4.68; SizeX_mm: 1.6; SizeY_mm: 0.8; SizeZ_mm: 1
C135 C136 = CMP-0007261-4: CAP, CERM, 30 pF, 100 V, +/- 5%, C0G/NP0, 0603; PartNumber: GRM1885C2A300JA01D; Manufacturer: MuRata; Polarized: N; Value: 30pF; U/M: EA; Value1: Unknown; VDC_V: 100V; TaMin_C: -55°C; TaMax_C: 125°C; AEC Category: Q200; SizeArea_mm2: 1.28; SizeAreaWB_mm2: 4.68; SizeX_mm: 1.6; SizeY_mm: 0.8; SizeZ_mm: 1
C139 = CMP-0006898-4: CAP, CERM, 2200 pF, 50 V, +/- 10%, X7R, 0603; PartNumber: C0603C222K5RACTU; Manufacturer: Kemet; Polarized: N; Value: 2200pF; U/M: EA; Cap_F: 2.2nF; Value1: Unknown; VDC_V: 50V; TaMin_C: -55°C; TaMax_C: 125°C; AEC Category: Q200; SizeArea_mm2: 1.28; SizeAreaWB_mm2: 4.68; SizeX_mm: 1.6; SizeY_mm: 0.8; SizeZ_mm: 1
C141 = CMP-0007373-4: CAP, CERM, 0.47 uF, 10 V, +/- 10%, X7R, 0603; PartNumber: GRM188R71A474KA61D; Manufacturer: MuRata; Polarized: N; Value: 0.47uF; U/M: EA; Cap_F: 470nF; Value1: Unknown; VDC_V: 10V; TaMin_C: -55°C; TaMax_C: 125°C; AEC Category: Q200; SizeArea_mm2: 1.28; SizeAreaWB_mm2: 4.68; SizeX_mm: 1.6; SizeY_mm: 0.8; SizeZ_mm: 1
D11 = CMP-0005670-2: Diode, Zener, 7.5 V, 550 mW, SMB; PartNumber: 1SMB5922BT3G; Manufacturer: ON Semiconductor; Power_W: 550mW; Value1: 0.55W; RJA_CperW: 226; AEC Category: Q101; SizeArea_mm2: 21.336; SizeAreaWB_mm2: 44.156; SizeX_mm: 5.6; SizeY_mm: 3.81; SizeZ_mm: 2.6
D12 = CMP-0002827-2: LED, Green, SMD; Manufacturer: Lite-On; PartNumber: LTST-C190GKT; Vf_V: 2.1V; Io_A: 20mA; Power_TotalModule: 100mW; Value1: 0.1W; U/M: EA
FB13 = CMP-0003426-2: Ferrite Bead, 60 ohm @ 100 MHz, 3.5 A, 0603; PartNumber: MPZ1608S600ATAH0; Manufacturer: TDK; Value: 60 ohm; Imax_A: 3.5A; DCR_ohm: 0.02; Value1: 0.02 ohm; ZTyp@100MHz_Ohm: 60; SizeAreaWB_mm2: 4.68; SizeArea_mm2: 1.28; SizeX_mm: 1.6; SizeY_mm: 0.8; SizeZ_mm: 1
J41 = CMP-0054920-1: Connector, Receptacle, Mini-USB Type B, R/A, Top Mount SMT; PartNumber: 1734035-2; Manufacturer: TE Connectivity; CNHeader: FALSE; CT: TRUE; Gender: Female; Green_Lifecycle: Active; Green_REACh: Passed
J42 = CMP-0077170-1: Header, 2.54mm, 15x2, Gold, SMD; Manufacturer: Samtec; CNHeader: False; Shrouded: Y; Gender: Male; Row_Count: 2; RowSpacing_mm: 2.54
Q5 = CMP-0000755-1: MOSFET, N-CH, 50 V, 0.22 A, SOT-23; Manufacturer: Fairchild Semiconductor; Alternate Manufacturer: None; U/M: EA; ChType: N; Value: 50V; Rdson45_ohm: 6; Value2: 1.7 nC; QgTyp_nC: 1.7; Vgs_V: 20V; IdsMax_A: 2.2dA; AEC Category: Q101; SizeArea_mm2: 7.5; SizeAreaWB_mm2: 14; SizeX_mm: 2.5; SizeY_mm: 3; SizeZ_mm: 1.1
R144 R146 = CMP-0026908-3: RES, 33, 5%, 0.063 W, AEC-Q200 Grade 0, 0402; PartNumber: CRCW040233R0JNED; Manufacturer: Vishay-Dale; Value_Code: 33R0; Power_W: 63mW; Value2: 0.063W; VDC_V: 50V; TempCo: 200 ppm/C; EIA_Code: E24; AEC Category: Q200; AEC Grade: 0; AEC Qualified: Y; SizeArea_mm2: 0.5; SizeX_mm: 1; SizeZ_mm: 0.6
R145 R148 R165 = CMP-0025786-4: RES, 33 k, 5%, 0.1 W, AEC-Q200 Grade 0, 0603; PartNumber: CRCW060333K0JNEA; Manufacturer: Vishay-Dale; Value_Code: 33k0; Power_W: 100mW; Value2: 0.1W; VDC_V: 75V; TempCo: 200 ppm/C; EIA_Code: E24; AEC Category: Q200; AEC Grade: 0; AEC Qualified: Y; SizeArea_mm2: 1.28; SizeX_mm: 1.6; SizeY_mm: 0.8; SizeZ_mm: 1
R147 = CMP-0026856-5: RES, 1.5 k, 5%, 0.063 W, AEC-Q200 Grade 0, 0402; PartNumber: CRCW04021K50JNED; Manufacturer: Vishay-Dale; Value_Code: 1k50; Power_W: 63mW; Value2: 0.063W; VDC_V: 50V; TempCo: 200 ppm/C; EIA_Code: E24; AEC Category: Q200; AEC Grade: 0; AEC Qualified: Y; SizeArea_mm2: 0.5; SizeX_mm: 1; SizeZ_mm: 0.6
R149 = CMP-0025738-4: RES, 1.2 M, 5%, 0.1 W, AEC-Q200 Grade 0, 0603; PartNumber: CRCW06031M20JNEA; Manufacturer: Vishay-Dale; Res_ohm: 1.2M; Value_Code: 1M20; Power_W: 100mW; Value2: 0.1W; VDC_V: 75V; TempCo: 200 ppm/C; EIA_Code: E24; AEC Category: Q200; AEC Grade: 0; AEC Qualified: Y; SizeArea_mm2: 1.28; SizeX_mm: 1.6; SizeY_mm: 0.8; SizeZ_mm: 1
R150-R157 R163 R164 R212 = CMP-0025697-4: RES, 0, 5%, 0.1 W, AEC-Q200 Grade 0, 0603; PartNumber: CRCW06030000Z0EA; Manufacturer: Vishay-Dale; Value_Code: 0000; Power_W: 100mW; Value2: 0.1W; VDC_V: 75V; TempCo: 200 ppm/C; EIA_Code: E24; AEC Category: Q200; AEC Qualified: Y; SizeArea_mm2: 1.28; SizeX_mm: 1.6; SizeY_mm: 0.8; SizeZ_mm: 1
R158 = CMP-0025697-4: RES, 0, 5%, 0.1 W, AEC-Q200 Grade 0, 0603; Manufacturer: Vishay-Dale; Value: 0; Value_Code: 0000; Power_W: 100mW; Value2: 0.1W; VDC_V: 75V; TempCo: 200 ppm/C; EIA_Code: E24; SizeX_mm: 1.6; SizeY_mm: 0.8; SizeZ_mm: 1; SizeArea_mm2: 1.28; AEC Qualified: Y; AEC Category: Q200
R159 R160 = CMP-0025729-4: RES, 1.0 k, 5%, 0.1 W, AEC-Q200 Grade 0, 0603; Manufacturer: Vishay-Dale; Value: 1.0k; Res_ohm: 1k; Value_Code: 1k00; Power_W: 100mW; Value2: 0.1W; VDC_V: 75V; TempCo: 200 ppm/C; EIA_Code: E24; SizeX_mm: 1.6; SizeY_mm: 0.8; SizeZ_mm: 1; SizeArea_mm2: 1.28; AEC Qualified: Y; AEC Category: Q200; AEC Grade: 0
R161 R162 R166 = CMP-0025823-4: RES, 510, 5%, 0.1 W, AEC-Q200 Grade 0, 0603; PartNumber: CRCW0603510RJNEA; Manufacturer: Vishay-Dale; Value: 510; Value_Code: 510R; Power_W: 100mW; Value2: 0.1W; VDC_V: 75V; TempCo: 200 ppm/C; EIA_Code: E24; AEC Category: Q200; AEC Grade: 0; AEC Qualified: Y; SizeArea_mm2: 1.28; SizeX_mm: 1.6; SizeY_mm: 0.8; SizeZ_mm: 1
S6 = CMP-0002134-3: Switch, Tactile, SPST-NO, 0.05A, 12V, SMT; PartNumber: FSM4JSMA; Manufacturer: TE Connectivity; CurrentRating_mA: 50A; PositionCount: 1; SwitchFunction: Off-Mom
TP41 = CMP-0055137-1: as TP1 on sheet LMK5B12212_Power
U6 = CMP-0066010-1: 150-mA Ultra-Low Noise LDO for RF and Analog Circuits Requires No Bypass Capacitor, NGF0006A (WSON-6); Manufacturer: Texas Instruments; CompType: IC; Green_Lifecycle: Active; Green_REACh: Passed; SizeArea_mm2: 5.5; SizeAreaWB_mm2: 11.2; SizeX_mm: 2.5; SizeY_mm: 2.2; SizeZ_mm: 0.8; U/M: EA
U7 = CMP-0043115-3: 4-Channel ESD Protection Array for High-Speed Data Interfaces, DRY0006A (USON-6); Manufacturer: Texas Instruments; 1394 / Firewire: TRUE; Breakdown Voltage(Min)(V): 6; Eco-Plan: Green (RoHS & no Sb/Br); IEC 61000-4-2 Air-Gap(+/- kV): 12; IEC 61000-4-2 Contact(+/- kV): 8; IO Capacitance(Typ)(pF): 1.6; IO Leakage Current(nA): 1; AEC Category: Q200; AEC Qualified: N; CompType: IC; Rating: Catalog; SizeArea_mm2: 1.45; SizeAreaWB_mm2: 4.9; SizeX_mm: 1.0; SizeZ_mm: 0.6
U8 = CMP-0038965-1: 25 MHz Mixed Signal Microcontroller with 128 KB Flash, 8192 B SRAM and 63 GPIOs, -40 to 85 degC, 80-pin QFP (PN), Green (RoHS & no Sb/Br); Manufacturer: Texas Instruments; ADC: 12-bit SAR; ADC Channels: 16; Brown Out Reset: Yes; DMA: 3; Flash(KB): 128; Frequency(MHz): 25; GPIO: 63; Multiplier: 32x32; SRAM(B): 8192; SubFamily: 5 Series; Timers - 16-bit: 4; USB: 1; USCI_A (UART/LIN/IrDA/SPI): 2
Y6 = CMP-0004572-3: Crystal, 24.000 MHz, 20pF, SMD; PartNumber: ECS-240-20-5PX-TR; Manufacturer: ECS Inc.; TaMin_C: -10°C; TaMax_C: 70°C; Frequency Stability: +/-50ppm; Frequency_Fixed: 24MHz

## Sheet LMK5B12212_XO.SchDoc
size 431 x 279 mm; Date: Not shown in title block; ApprovedBy: Not shown in title block; CheckedBy: Not shown in title block; Author: Not shown in title block; CompanyName: Not shown in title block; Engineer: Not shown in title block; Organization: Not shown in title block; Address1: Not shown in title block; Address2: Not shown in title block; Address3: Not shown in title block; Address4: Not shown in title block; DocumentNumber: 1; Revision: Use project parameter SCH_Rev; SheetNumber: 2; SheetTotal: 3; PageSetup: Record=PageOptions¦CenterHorizontal=True¦CenterVertical=True¦PrintScale=1.00¦XCorrection=1.00¦YCorrection=1.00¦PrintKind=0¦BorderSize=5000000¦LeftOffset=0¦BottomOffset=0¦Orientation=2¦PaperLength=1000¦PaperWidth=1000¦Scale=100¦PaperSource=15¦PrintQuality=600¦MediaType=1¦DitherType=10¦PaperKind=Letter¦PrintScaleMode=1
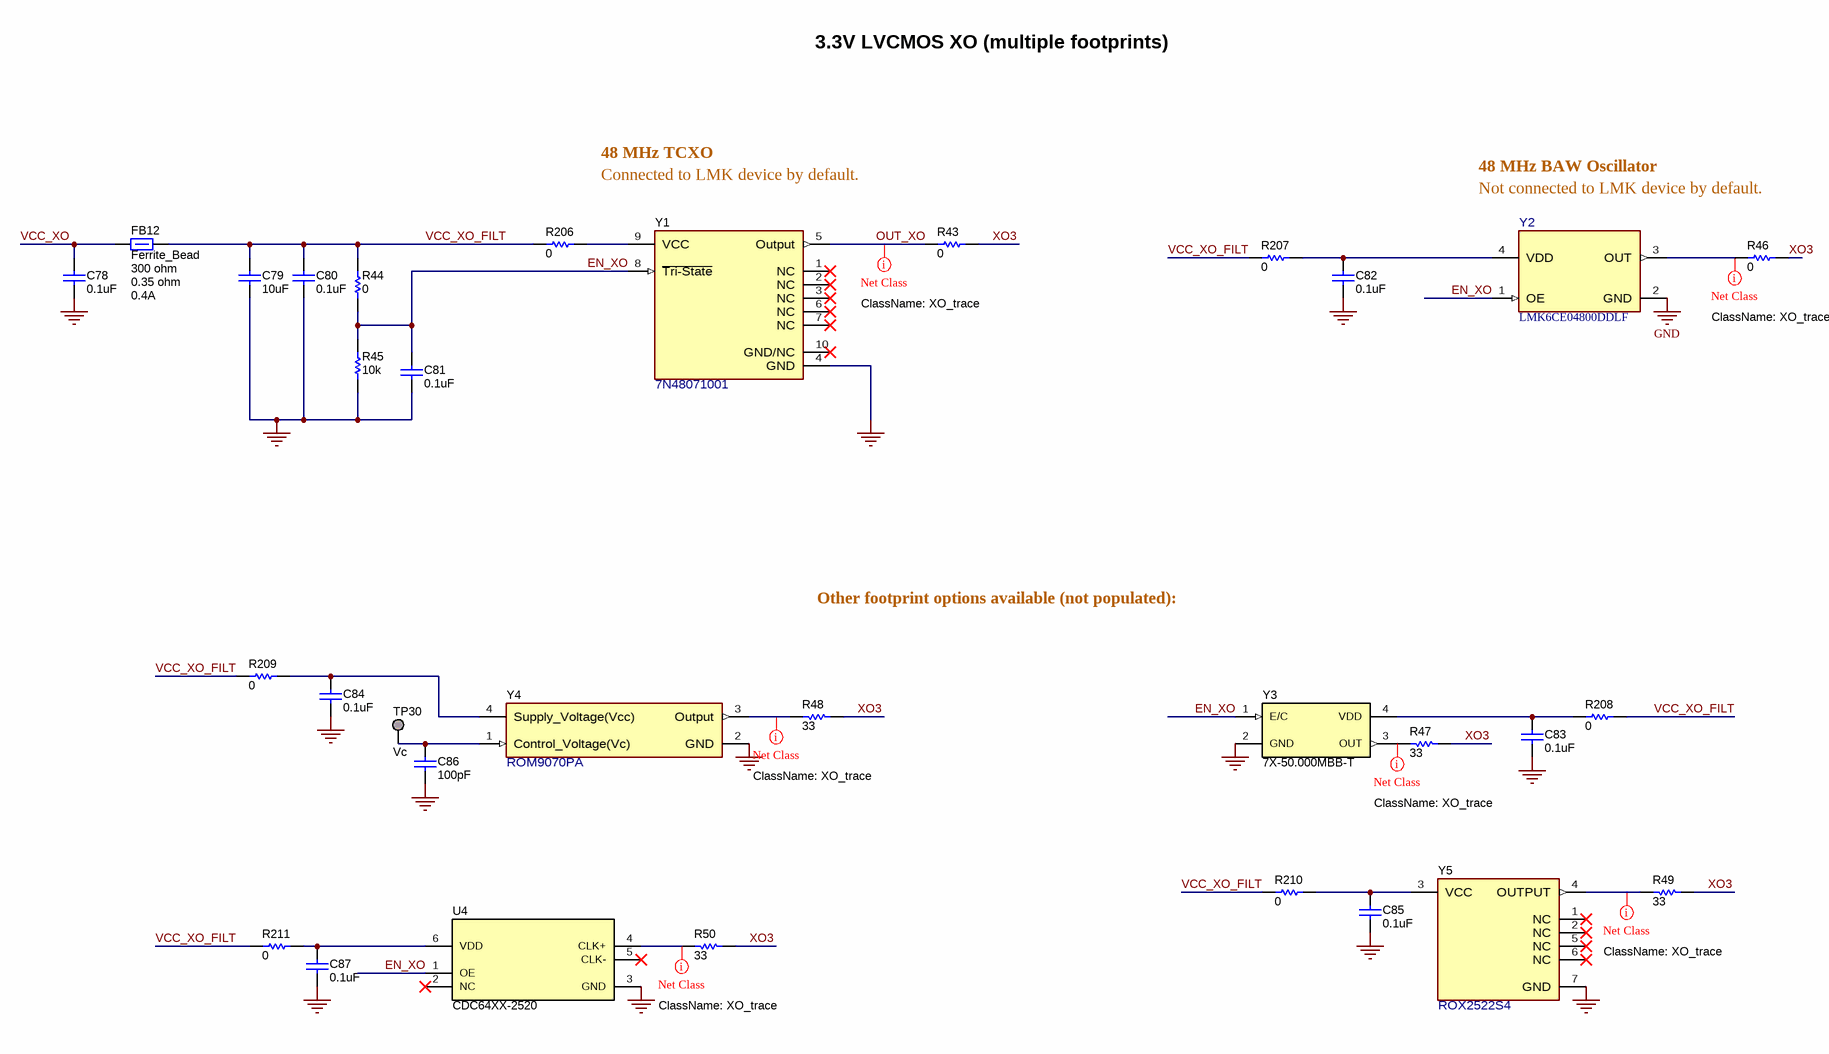
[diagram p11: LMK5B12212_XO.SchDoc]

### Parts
C78  ValueDisplayed: 0.1uF  [0603]  (hidden comment: Capacitor)
C79  ValueDisplayed: 10uF  [0603]  (hidden comment: Capacitor)
C80  ValueDisplayed: 0.1uF  [0603]  (hidden comment: Capacitor)
C81  ValueDisplayed: 0.1uF  [0603]  (hidden comment: Capacitor)
C82  ValueDisplayed: 0.1uF  [0603]  (hidden comment: Capacitor)
C83  ValueDisplayed: 0.1uF  [0603]  (hidden comment: Capacitor)
C84  ValueDisplayed: 0.1uF  [0603]  (hidden comment: Capacitor)
C85  ValueDisplayed: 0.1uF  [0603]  (hidden comment: Capacitor)
C86  ValueDisplayed: 100pF  [0603]  (hidden comment: Capacitor)
C87  ValueDisplayed: 0.1uF  [0603]  (hidden comment: Capacitor)
FB12  Ferrite_Bead  value 300 ohm  Value1: 0.35 ohm  Value2: 0.4A  [LI0603D]
R43  ValueDisplayed: 0  [0402]  (hidden comment: CRCW04020000Z0EDHP)
R44  ValueDisplayed: 0  [0603]  (hidden comment: ERJ-3GEY0R00V)
R45  ValueDisplayed: 10k  [0603]  (hidden comment: Resistor)
R46  ValueDisplayed: 0  [0402S]  (hidden comment: CRCW04020000Z0EDHP)
R47  ValueDisplayed: 33  [0402S]  (hidden comment: CRCW040233R0JNED)
R48  ValueDisplayed: 33  [0402S]  (hidden comment: CRCW040233R0JNED)
R49  ValueDisplayed: 33  [0402S]  (hidden comment: CRCW040233R0JNED)
R50  ValueDisplayed: 33  [0402S]  (hidden comment: CRCW040233R0JNED)
R206  ValueDisplayed: 0  [0603]  (hidden comment: RC0603JR-070RL)
R207  ValueDisplayed: 0  [0603]  (hidden comment: RC0603JR-070RL)
R208  ValueDisplayed: 0  [0603]  (hidden comment: RC0603JR-070RL)
R209  ValueDisplayed: 0  [0603]  (hidden comment: RC0603JR-070RL)
R210  ValueDisplayed: 0  [0603]  (hidden comment: RC0603JR-070RL)
R211  ValueDisplayed: 0  [0603]  (hidden comment: RC0603JR-070RL)
TP30  Vc  [Keystone_5019]
U4  CDC64XX-2520  [DLF0006A]
Y1  7N48071001  [FP-7N48071001_SMT10_7MM0_5MM0-MFG]
Y2  PartNumber: LMK6CE04800DDLF  [DLE0004A-MFG]  (hidden comment: LMK6CE04800ADLE)
Y3  7X-50.000MBB-T  [OSC_TXC-7X]
Y4  ROM9070PA  [FP-ROM9070PA_SMD4-MFG]
Y5  ROX2522S4  [FP-ROX2522S4_SMD_ OCXO7_25MM4_22MM0-MFG]

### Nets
GND: C78.2 C79.1 C80.2 C81.2 C82.2 C83.2 C84.2 C85.2 C86.2 C87.2 R45.2 U4.3(GND) Y1.4(GND) Y2.2(GND) Y3.2(GND) Y4.2(GND) Y5.7(GND)
VCC_XO: C78.1 FB12.2
EN_XO: C81.1 R44.2 R45.1 U4.1(OE) Y1.8(~{Tri-State}) Y2.1(OE) Y3.1(E/C)
OUT_XO: R43.1 Y1.5(Output)
VCC_XO_FILT: C79.2 C80.1 FB12.1 R44.1 R206.1 R207.1 R208.2 R209.1 R210.1 R211.1
XO3: R43.2 R46.1 R47.1 R48.1 R49.1 R50.1
NetC82_1: C82.1 R207.2 Y2.4(VDD)
NetC83_1: C83.1 R208.1 Y3.4(VDD)
NetC84_1: C84.1 R209.2 Y4.4(Supply_Voltage(Vcc))
NetC85_1: C85.1 R210.2 Y5.3(VCC)
NetC86_1: C86.1 TP30.1 Y4.1(Control_Voltage(Vc))
NetC87_1: C87.1 R211.2 U4.6(VDD)
NetR46_2: R46.2 Y2.3(OUT)
NetR47_2: R47.2 Y3.3(OUT)
NetR48_2: R48.2 Y4.3(Output)
NetR49_2: R49.2 Y5.4(OUTPUT)
NetR50_2: R50.2 U4.4(CLK+)
NetR206_2: R206.2 Y1.9(VCC)

Not connected (* = marked no-connect by the designer): U4 2(NC)* 5(CLK-)*; Y1 1(NC)* 2(NC)* 3(NC)* 6(NC)* 7(NC)* 10(GND/NC)*; Y5 1(NC)* 2(NC)* 5(NC)* 6(NC)*

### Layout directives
net class XO_trace: NetR46_2, NetR47_2, NetR48_2, NetR49_2, NetR50_2, OUT_XO

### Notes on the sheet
- 3.3V LVCMOS XO (multiple footprints)
- 48 MHz TCXO
- 48 MHz BAW Oscillator
- Connected to LMK device by default.
- Not connected to LMK device by default.
- Other footprint options available (not populated):

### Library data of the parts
C78 C80-C85 C87 = CMP-0006856-6: CAP, CERM, 0.1 uF, 25 V, +/- 5%, X7R, 0603; Manufacturer: Kemet; PartNumber: C0603C104J3RACTU; Polarized: N; TaMax_C: 125°C; TaMin_C: -55°C; VDC_V: 25V; Cap_F: 100nF; Value: 0.1uF; Value1: Unknown; U/M: EA; AEC Category: Q200; SizeArea_mm2: 1.28; SizeAreaWB_mm2: 4.68; SizeX_mm: 1.6; SizeY_mm: 0.8; SizeZ_mm: 1
C79 = CMP-0007003-5: as C129 on sheet LMK5B12212_USB2ANY
C86 = CMP-0006763-4: CAP, CERM, 100 pF, 50 V, +/- 5%, C0G/NP0, 0603; PartNumber: 06035A101JAT2A; Manufacturer: AVX; Polarized: N; Value: 100pF; U/M: EA; ESR_ohm: 1.19d; Value1: 0.119 ohm; VDC_V: 50V; TaMin_C: -55°C; TaMax_C: 125°C; AEC Category: Q200; SizeArea_mm2: 1.28; SizeAreaWB_mm2: 4.68; SizeX_mm: 1.6; SizeY_mm: 0.8; SizeZ_mm: 1
FB12 = CMP-0003403-1: Ferrite Bead, 300 ohm @ 100 MHz, 0.4 A, 1.6x0.8x0.95mm; PartNumber: LI0603D301R-10; Manufacturer: Laird-Signal Integrity Products; Imax_A: 4dA; DCR_ohm: 3.5d; ZTyp@100MHz_Ohm: 300; SizeArea_mm2: 1.28; SizeAreaWB_mm2: 4.68; SizeX_mm: 1.6; SizeY_mm: 0.8; SizeZ_mm: 0.95
R43 R46 = CMP-0081856-1: RES, 0, 0%, 0.2 W, AEC-Q200 Grade 0, 0402; Manufacturer: Vishay-Dale; VDC_V: 50V; Power_W: 200mW; Value: 0; Value2: 0.2W; AEC Category: Q200; AEC Qualified: Y; SizeArea_mm2: 0.5; SizeX_mm: 1; SizeZ_mm: 0.6; SizeAreaWB_mm2: 3
R44 = CMP-0025874-4: RES, 0, 5%, 0.1 W, AEC-Q200 Grade 0, 0603; Manufacturer: Panasonic; CompType: Resistor; VDC_V: 50V; Power_W: 100mW; Value: 0; Value_Code: 0000; Value2: 0.1W; EIA_Code: E24; TempCo: 600 ppm/C; AEC Category: Q200; AEC Qualified: Y; SizeArea_mm2: 1.28; SizeX_mm: 1.6; SizeY_mm: 0.8; SizeZ_mm: 1; SizeAreaWB_mm2: 4.68
R45 = CMP-0025701-4: RES, 10 k, 5%, 0.1 W, AEC-Q200 Grade 0, 0603; Manufacturer: Vishay-Dale; PartNumber: CRCW060310K0JNEA; VDC_V: 75V; Power_W: 100mW; Value: 10k; Value_Code: 10k0; Value2: 0.1W; EIA_Code: E24; TempCo: 200 ppm/C; AEC Category: Q200; AEC Qualified: Y; AEC Grade: 0; SizeArea_mm2: 1.28; SizeX_mm: 1.6; SizeY_mm: 0.8; SizeZ_mm: 1
R47-R50 = CMP-0026908-3: RES, 33, 5%, 0.063 W, AEC-Q200 Grade 0, 0402; Manufacturer: Vishay-Dale; VDC_V: 50V; Power_W: 63mW; Value: 33; Value_Code: 33R0; Value2: 0.063W; EIA_Code: E24; TempCo: 200 ppm/C; AEC Category: Q200; AEC Qualified: Y; AEC Grade: 0; SizeArea_mm2: 0.5; SizeX_mm: 1; SizeZ_mm: 0.6
R206-R211 = CMP-0025885-5: RES, 0, 5%, 0.1 W, 0603; Manufacturer: Yageo; Power_W: 100mW; TempCo: 200 ppm/C; Value_Code: 0000; Value: 0; EIA_Code: E24; SizeX_mm: 1.6; SizeY_mm: 0.8; SizeZ_mm: 1; Value2: 0.1W; SizeArea_mm2: 1.28; AEC Qualified: N; AEC Category: Q200; VDC_V: 75V; SizeAreaWB_mm2: 4.68
TP30 = CMP-0055162-1: Test Point, Miniature, SMT; Manufacturer: Keystone; PartNumber: 5019; CNHeader: FALSE; Green_Lifecycle: Active; Green_REACh: Passed; CT: TRUE
U4 = CMP-0078850-3: CDC64XX-2520, DLF0006A (VSON-6); Alternate Manufacturer: Texas Instruments; SizeZ_mm: 1; AEC Qualified: N; SizeArea_mm2: 5; SizeY_mm: 2.5; AEC Category: Q200; SizeAreaWB_mm2: 10.5; SizeX_mm: 2; CompType: IC
Y1 = CMP-0093851-1: SMD TCXO 7.0 * 5.0 48.000000MHz; Manufacturer: TXC; Frequency Stability: 0.25ppm; Frequency_Fixed: 48MHz; SizeZ_mm: 1.7mm; AEC Qualified: No; Load Capacitance: 15pF; Min Supply Voltage: 2.97V; Max Supply Voltage: 3.63V; Max Supply Current: 10mA
Y2 = CMP-0096255-1: High-Performance BAW Oscillator, LVCMOS; <1ps, +/- 50ppm; 2.5V/3.3V, -40C to 105C and DLE package; Manufacturer: Texas Instruments; Max Supply Voltage: 3.465V; TaMax_C: +105°C; Standoff Height: 0mm; SizeZ_mm: 1mm; TaMin_C: -40°C; Frequency_Fixed: 48MHz; AEC Qualified: No; TJmax_C: +125°C; Load Capacitance: 30pF; Min Supply Voltage: 2.375V
Y3 = CMP-0006115-3: Crystal, Sealed Locked 50 MHz, 15pF, SMD; Manufacturer: TXC Corporation; TaMin_C: -40°C; Frequency Stability: +/-50ppm; Frequency_Fixed: 50MHz; TaMax_C: 85°C; CompType: Oscillator
Y4 = CMP-0088752-1: MERCURY+ 38.88MHz OCXO CMOS Oscillator 2.7 ~ 5V 4-SMD; Manufacturer: Rakon; AEC Qualified: No; SizeZ_mm: 4.1mm; Min Supply Voltage: 2.7V; Frequency Stability: 0.01ppm
Y5 = CMP-0088753-1: STANDARD OCXO 10MHz Frequency; Manufacturer: Rakon; Max Supply Voltage: 3.465V; SizeZ_mm: 15.4mm; Min Supply Voltage: 3.135V; AEC Qualified: No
